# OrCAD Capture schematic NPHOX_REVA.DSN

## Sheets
1 002 Voltage Regulators: size B; title: npHOx - Voltage Regulators; rev: C; note: 100221250rA
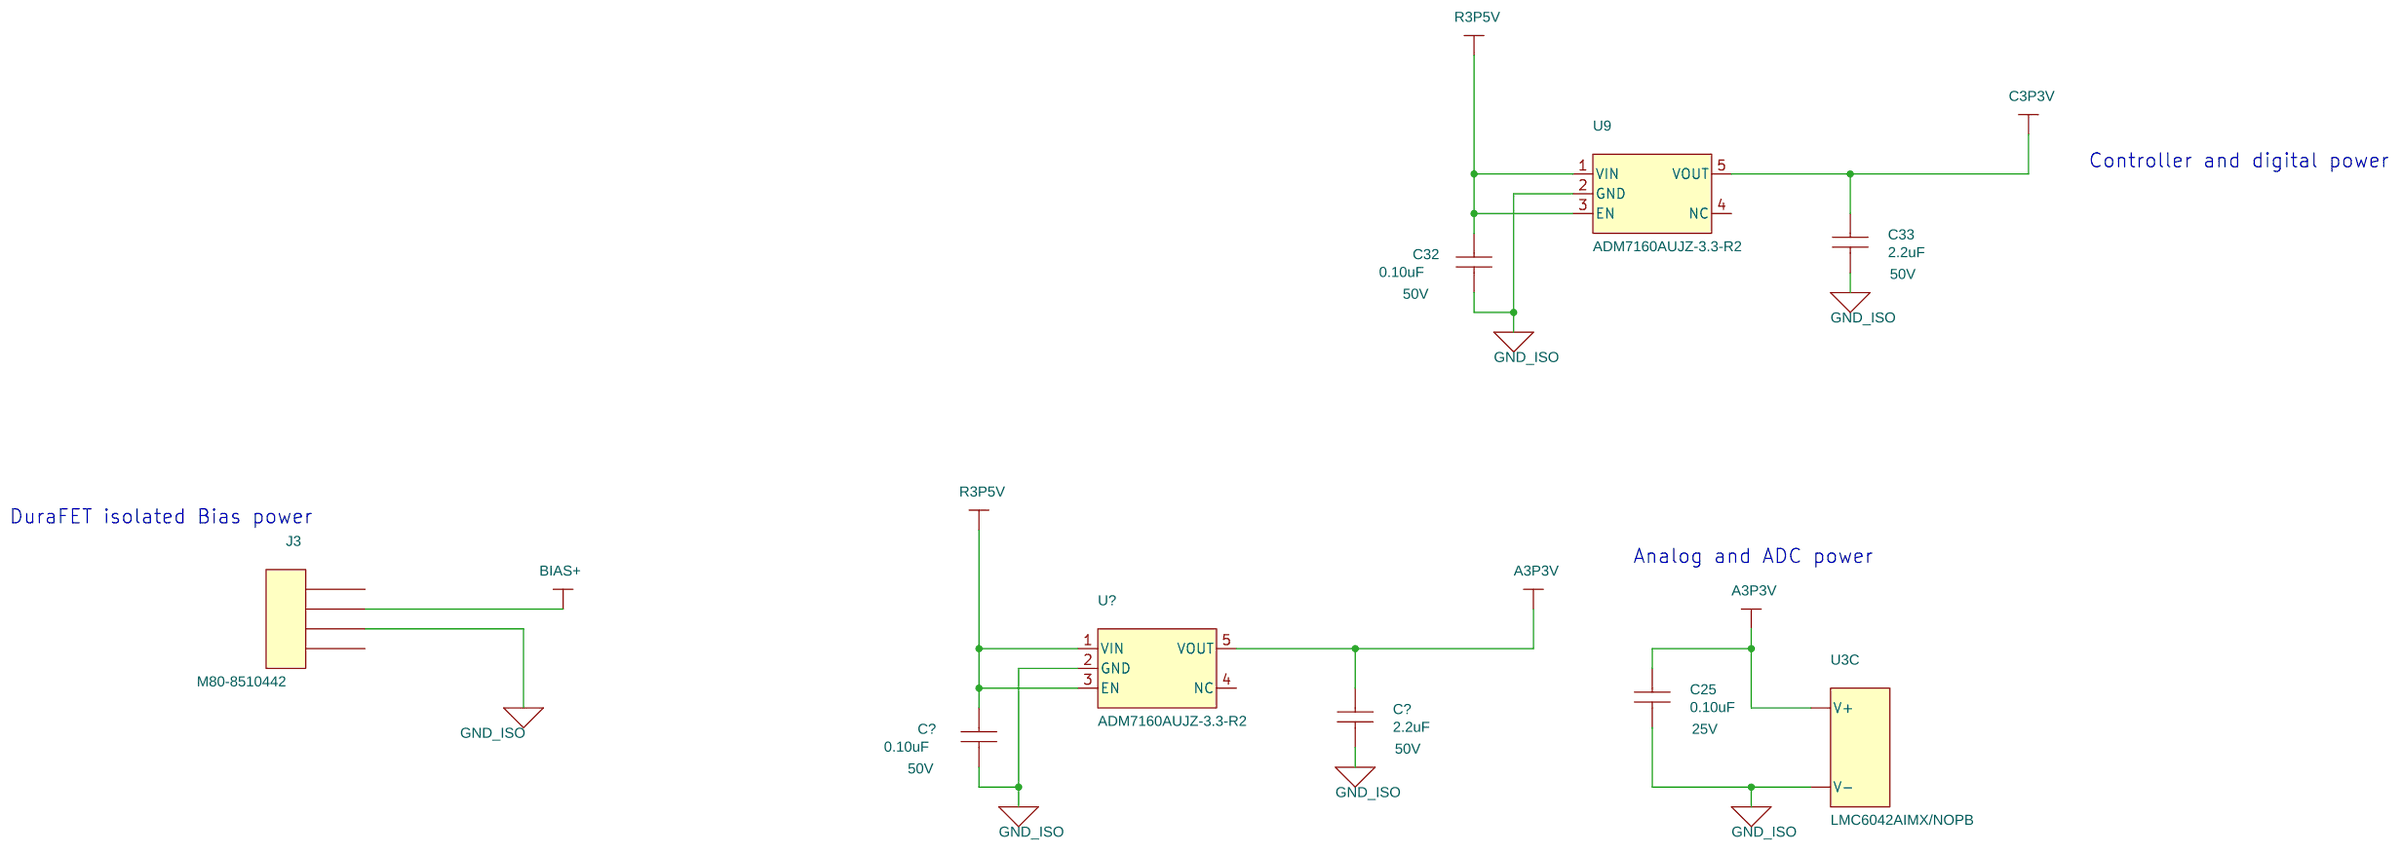
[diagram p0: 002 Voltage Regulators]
2 006 pH ADC: size B; title: npHOx - pH ADC
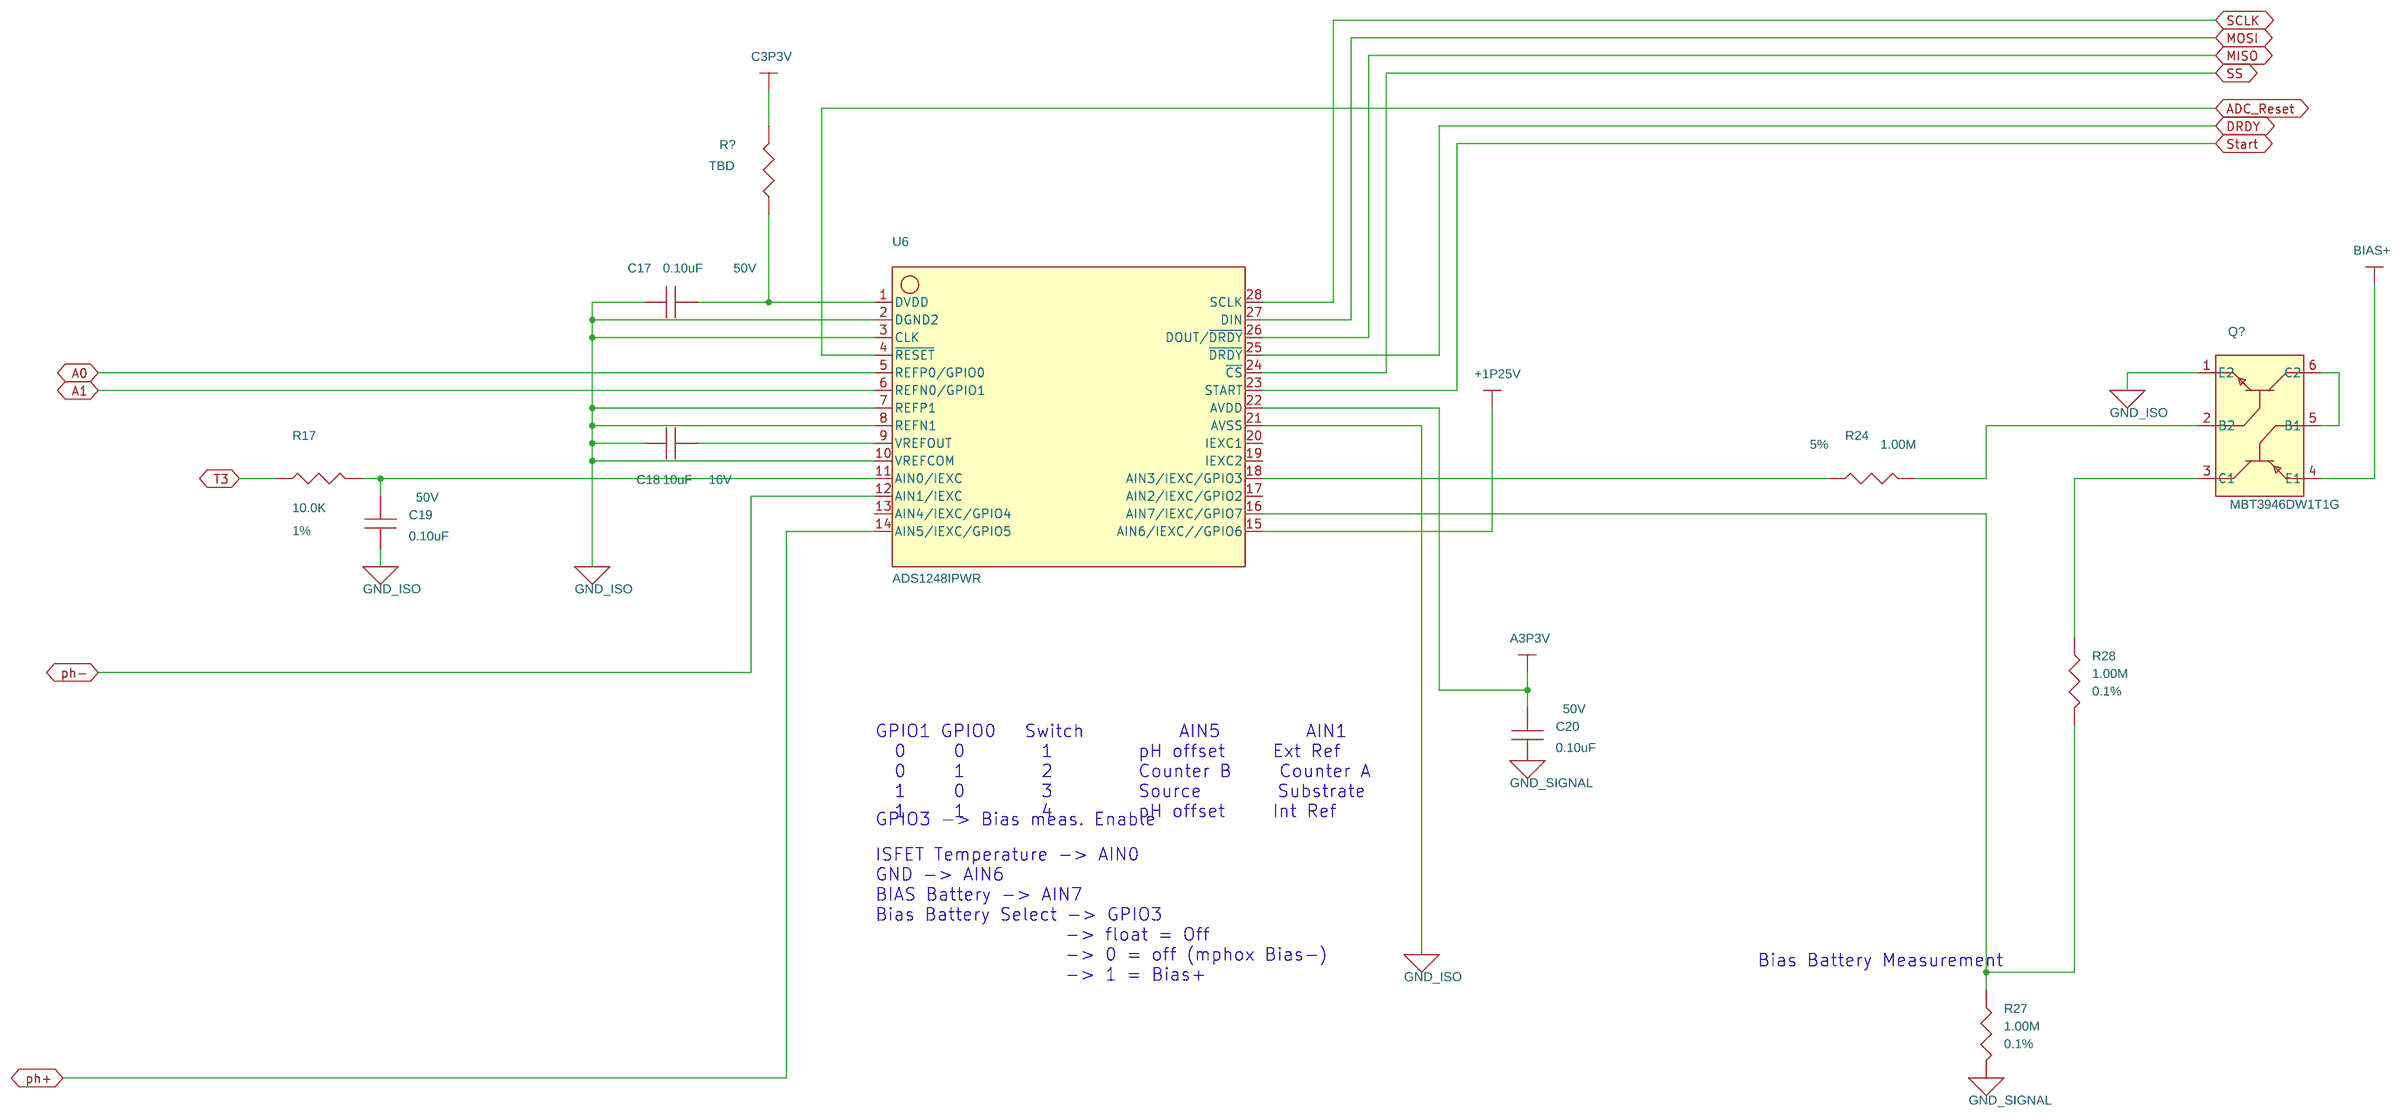
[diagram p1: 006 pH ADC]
3 007 Buffer: size B; title: npHOx - Buffer
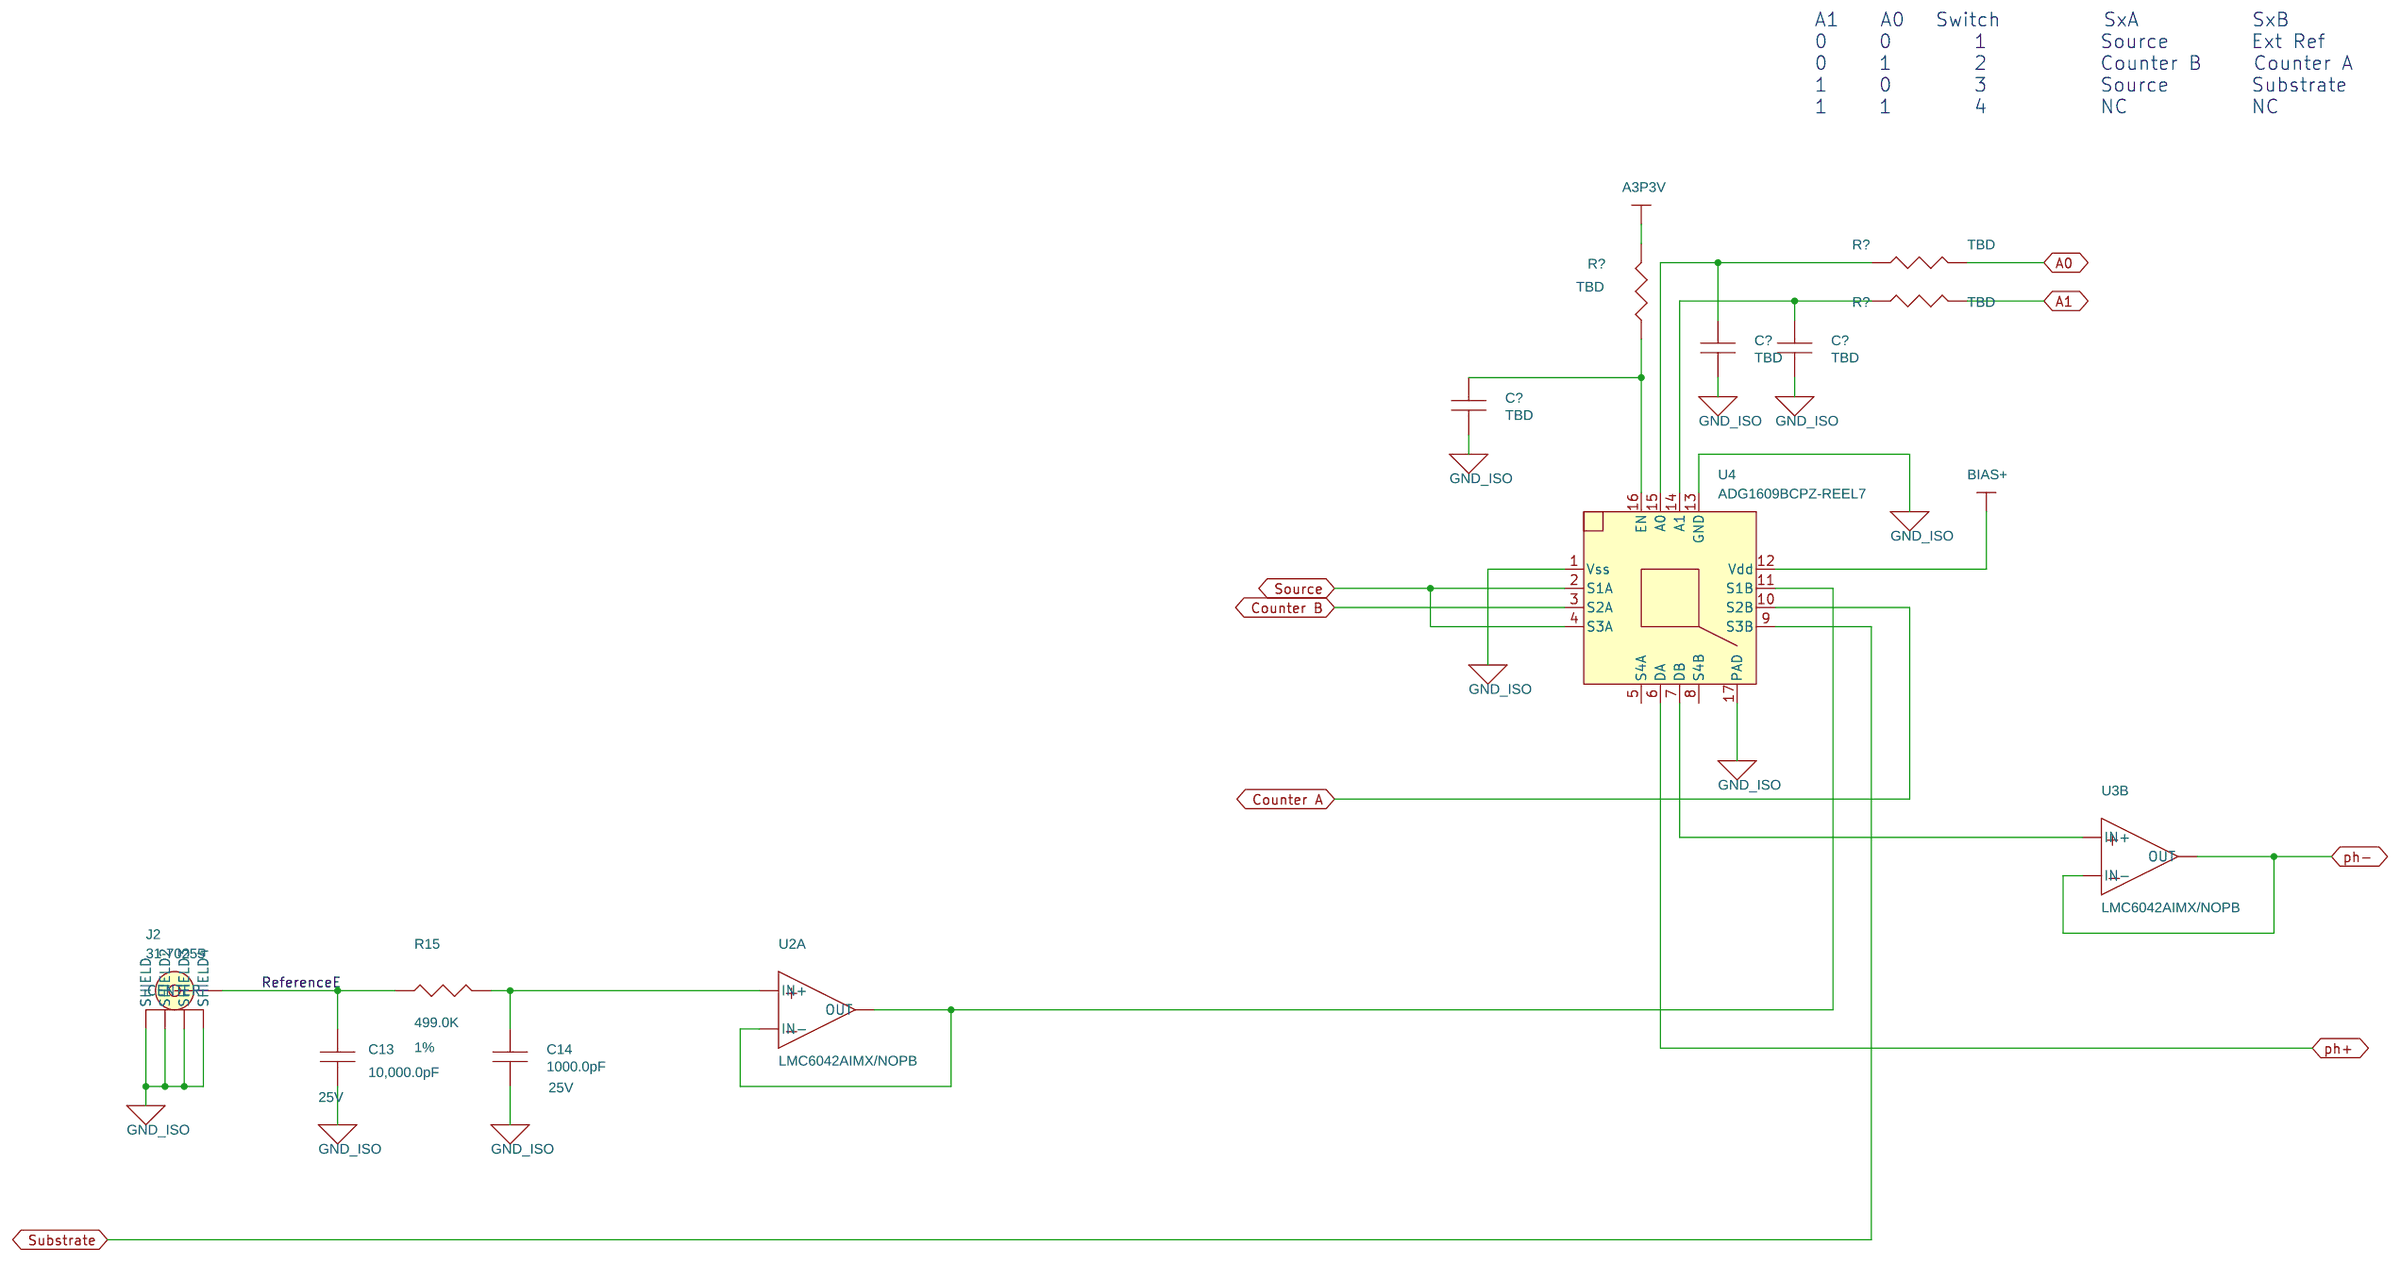
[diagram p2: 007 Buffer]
4 008 Bias: size B; title: npHOx - Bias
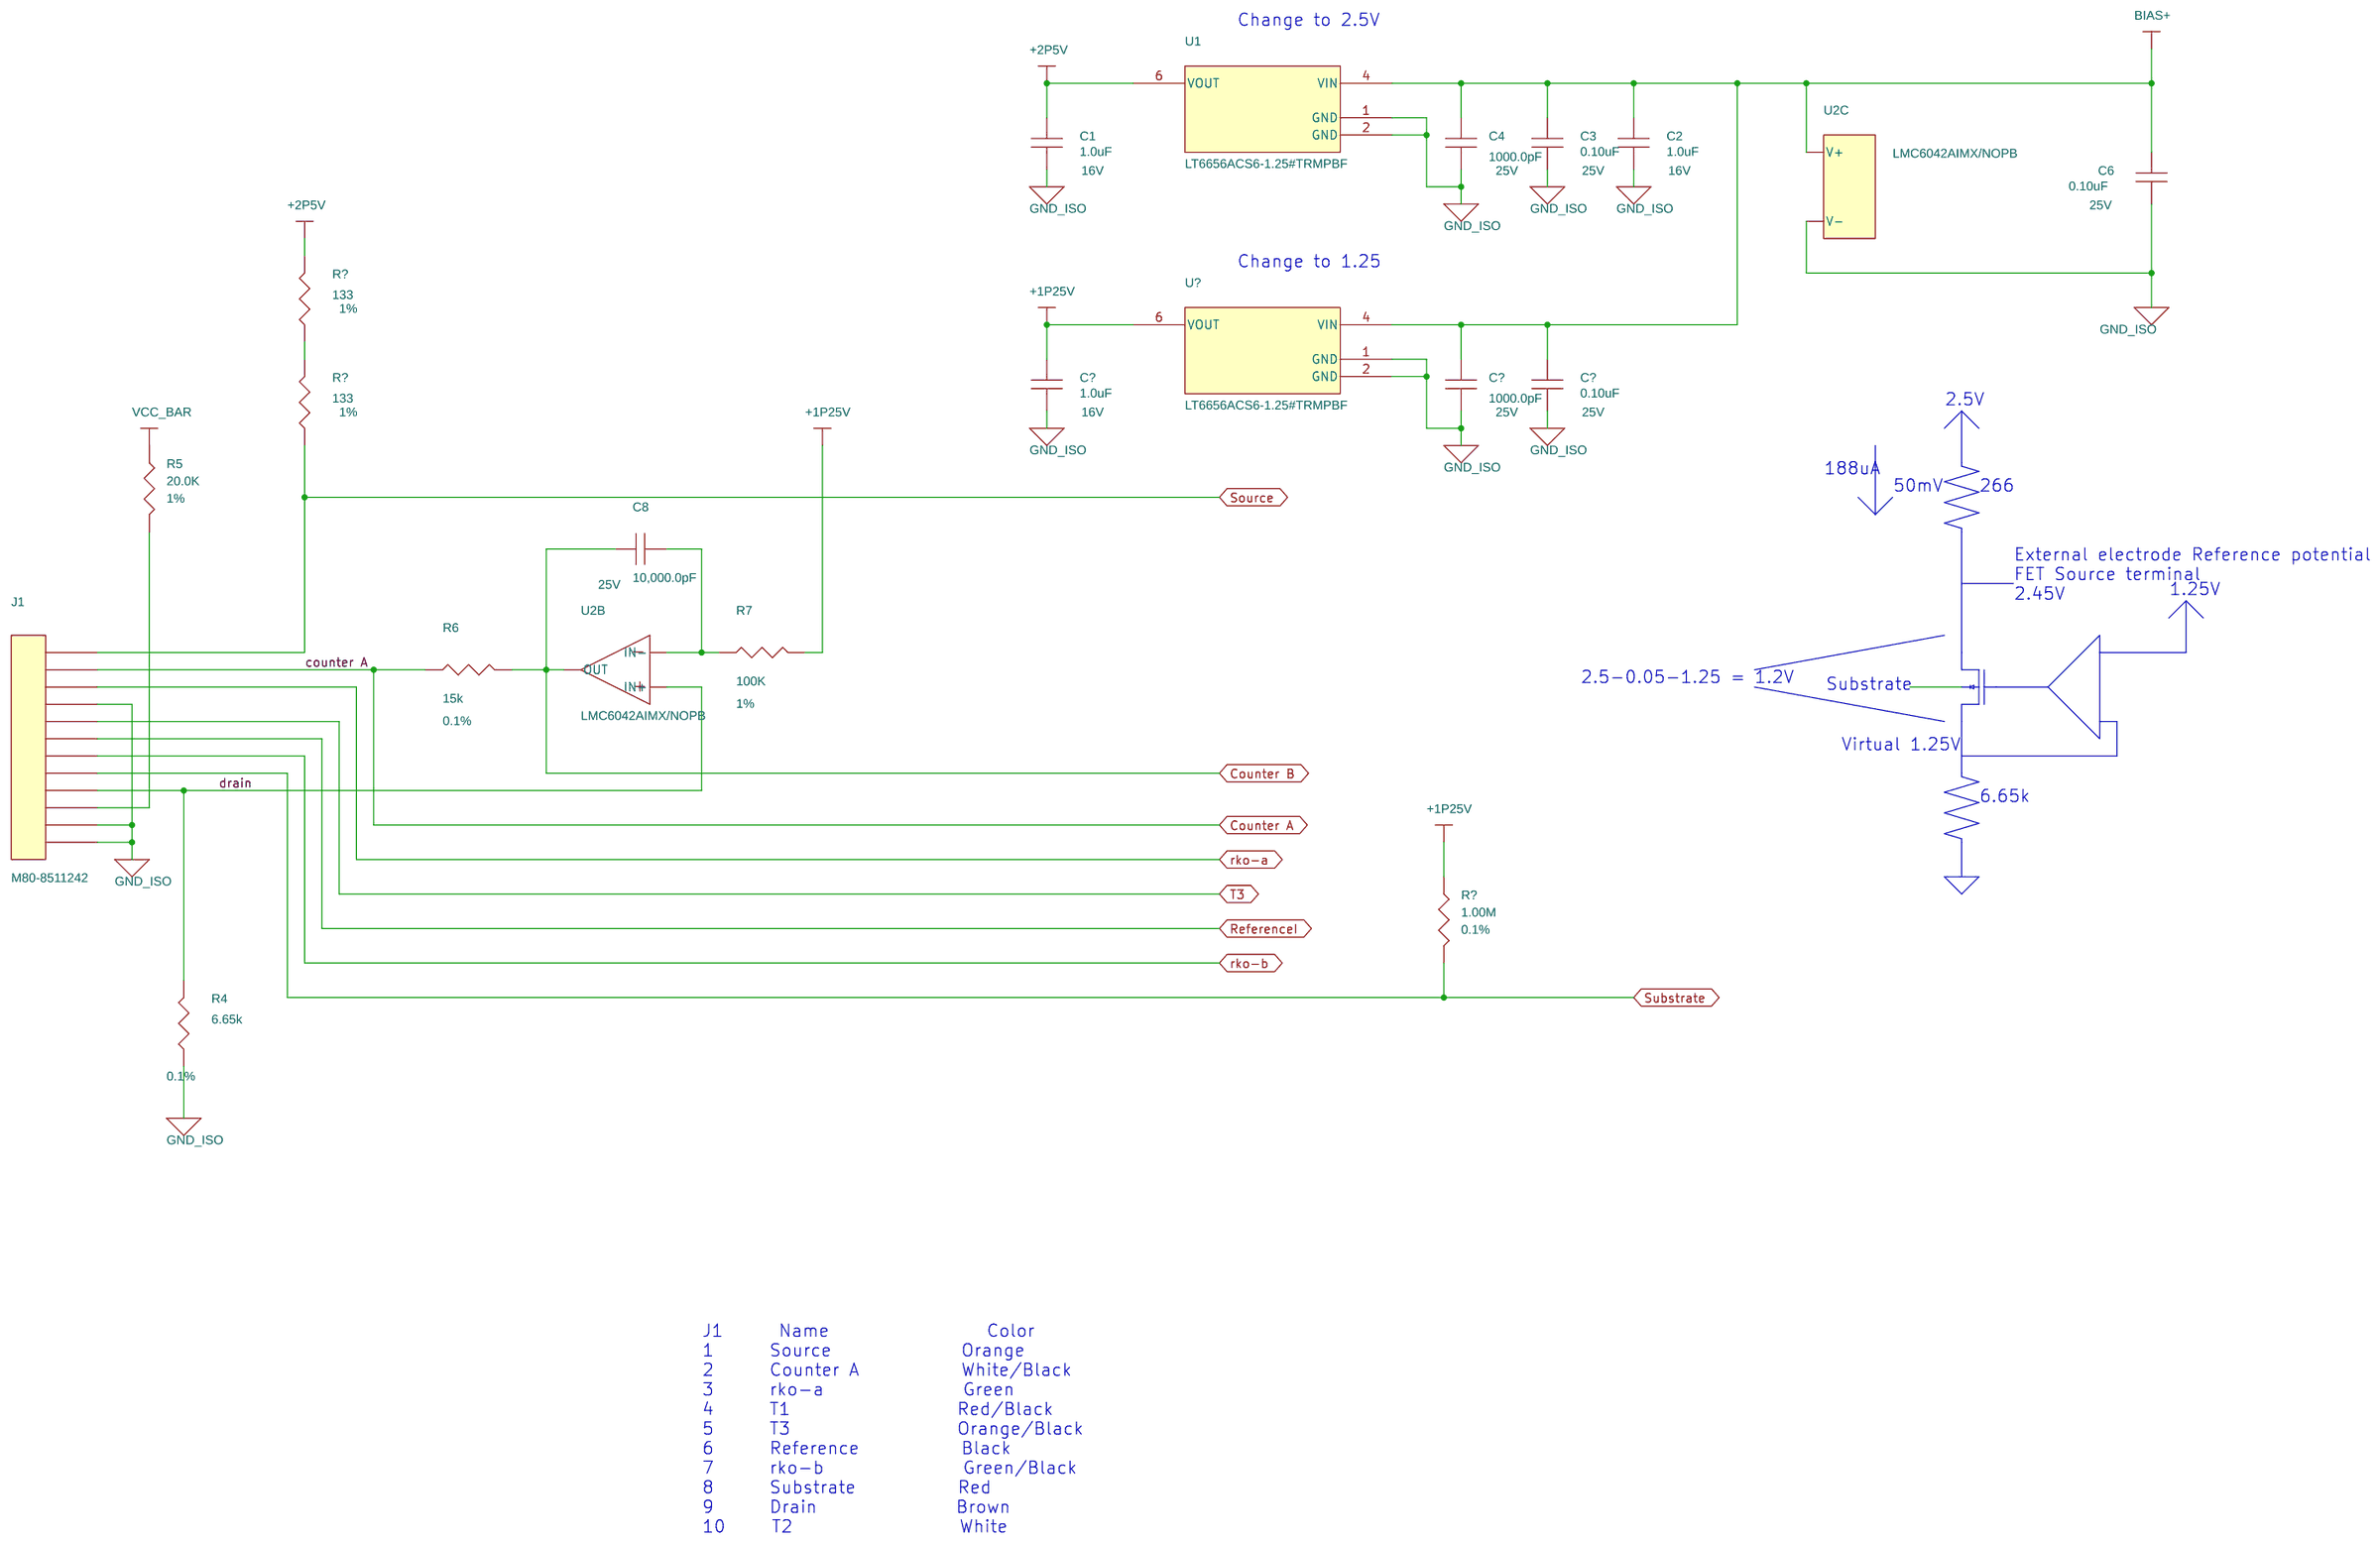
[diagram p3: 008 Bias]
5 001 Power: size B; title: npHOx - Power; rev: A
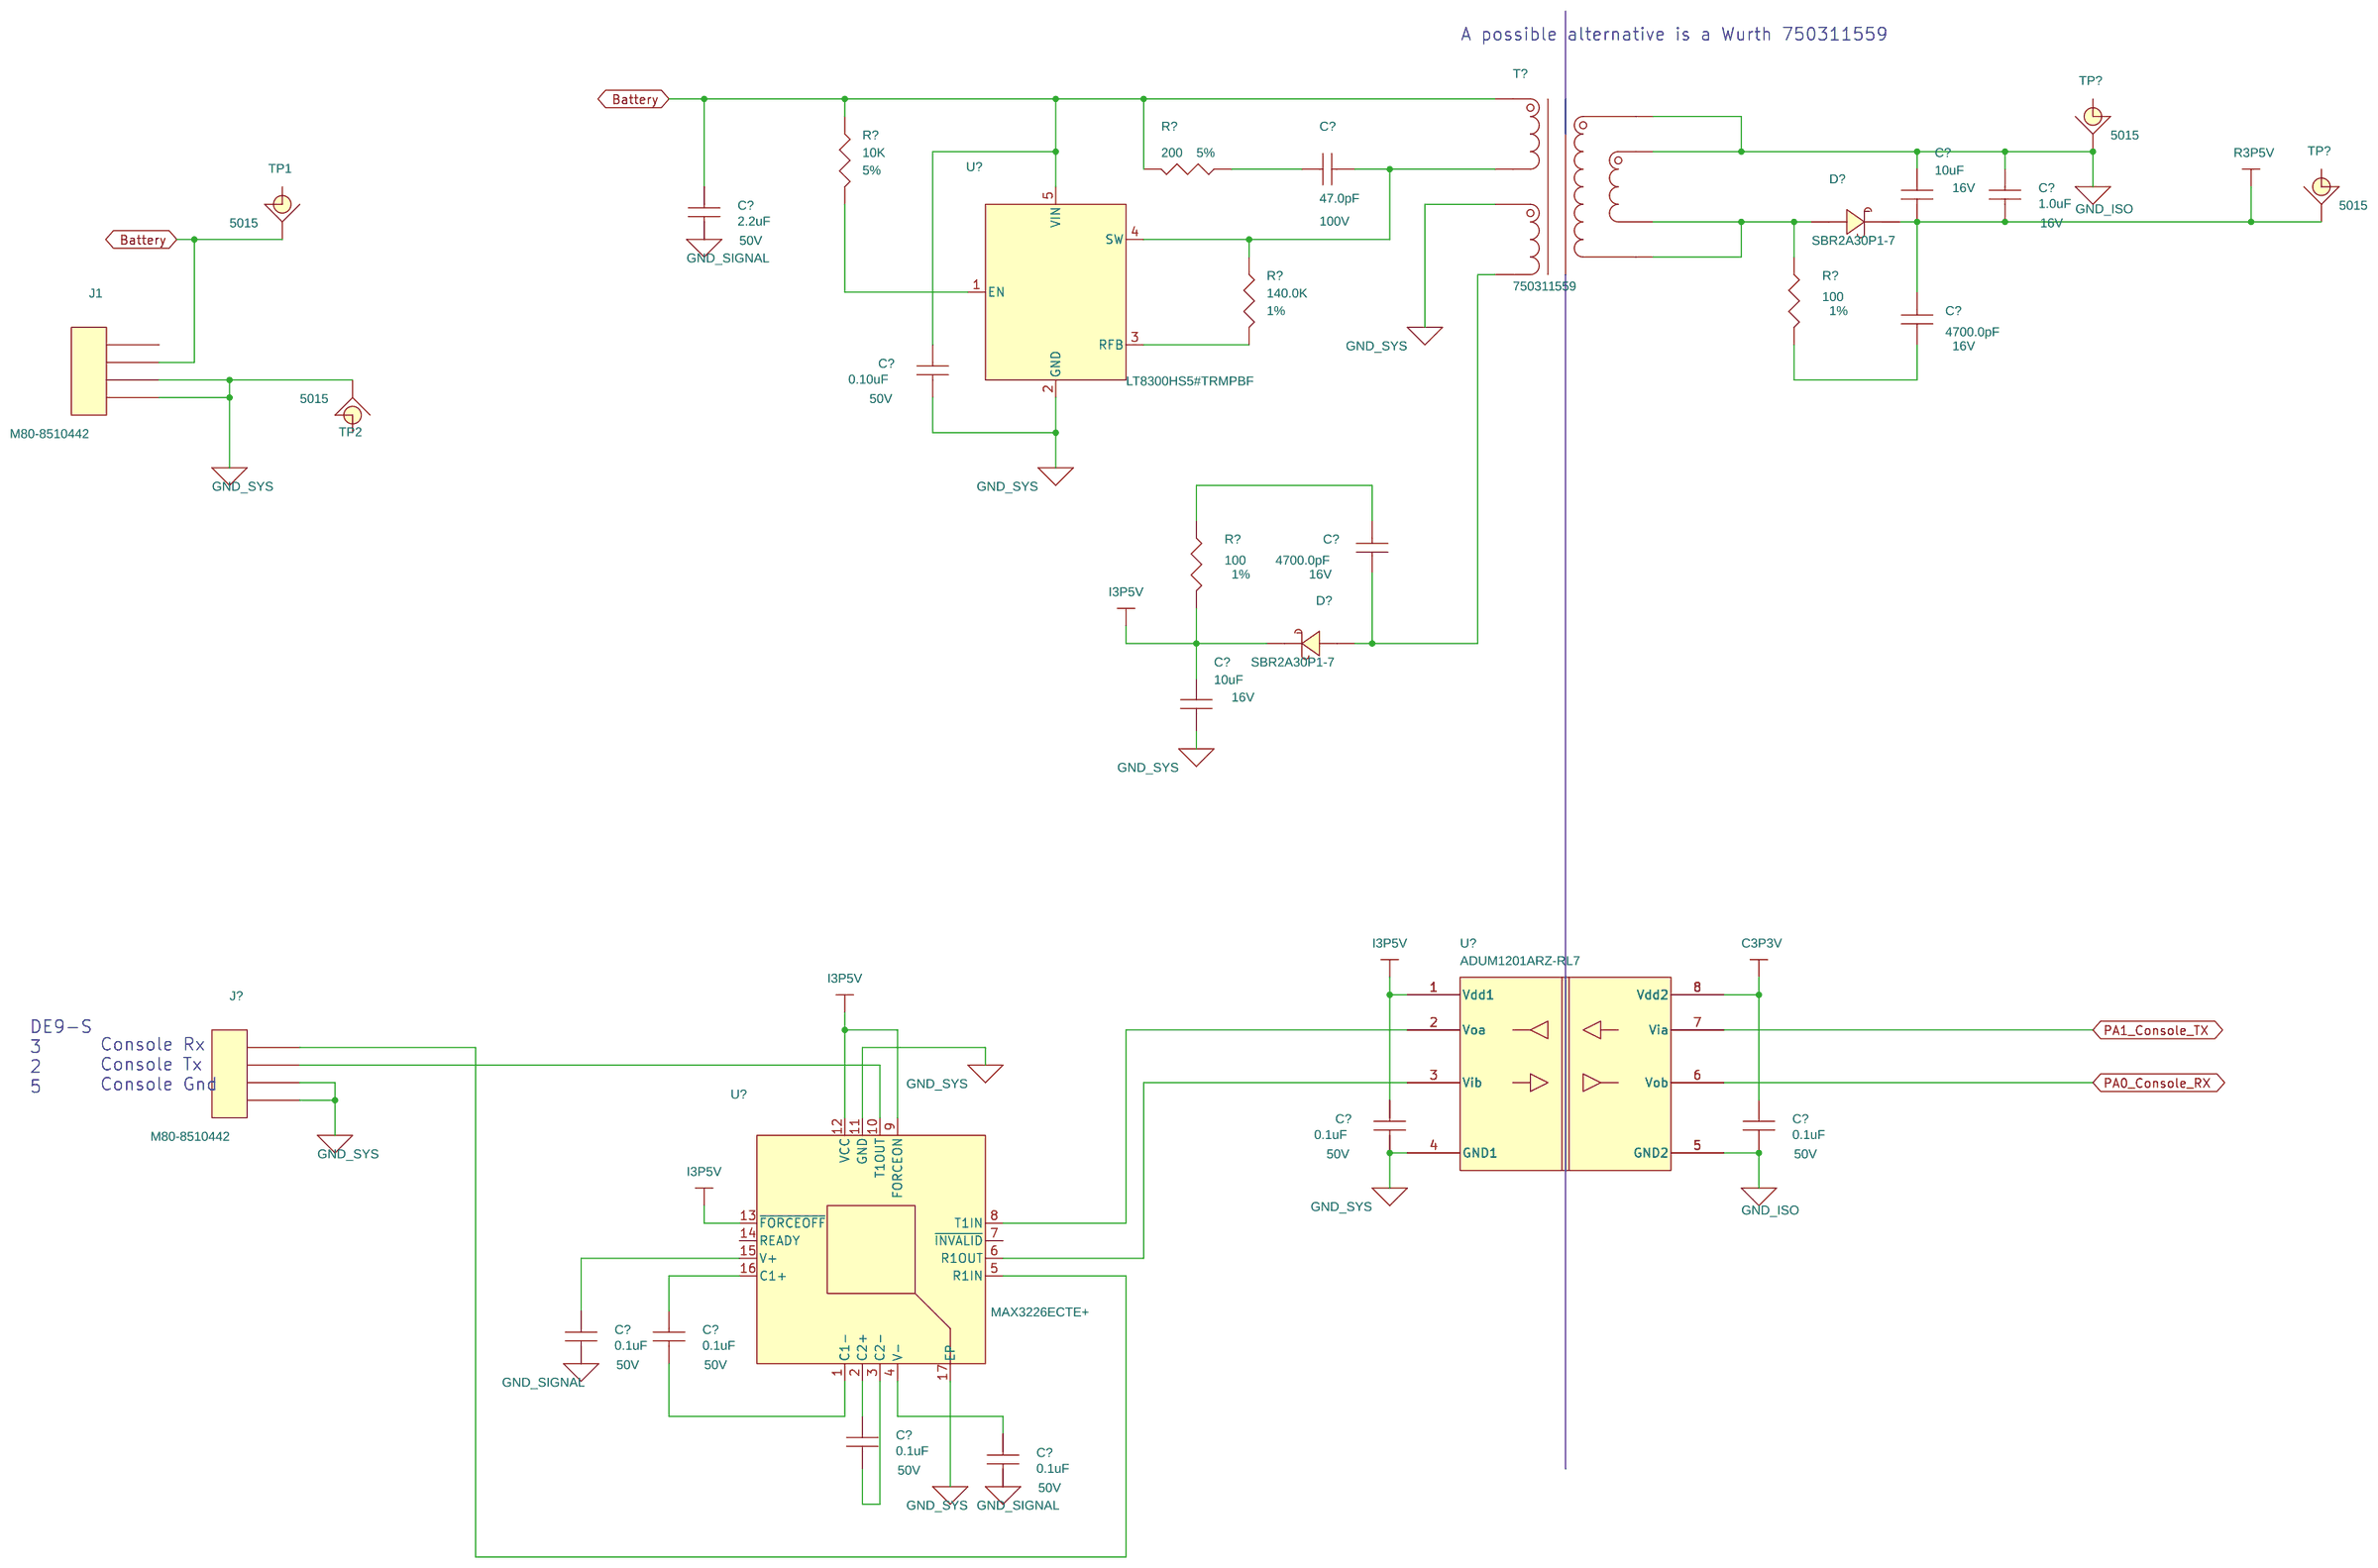
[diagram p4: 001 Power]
6 003 Processor: size B; title: npHOx - Processor; rev: A
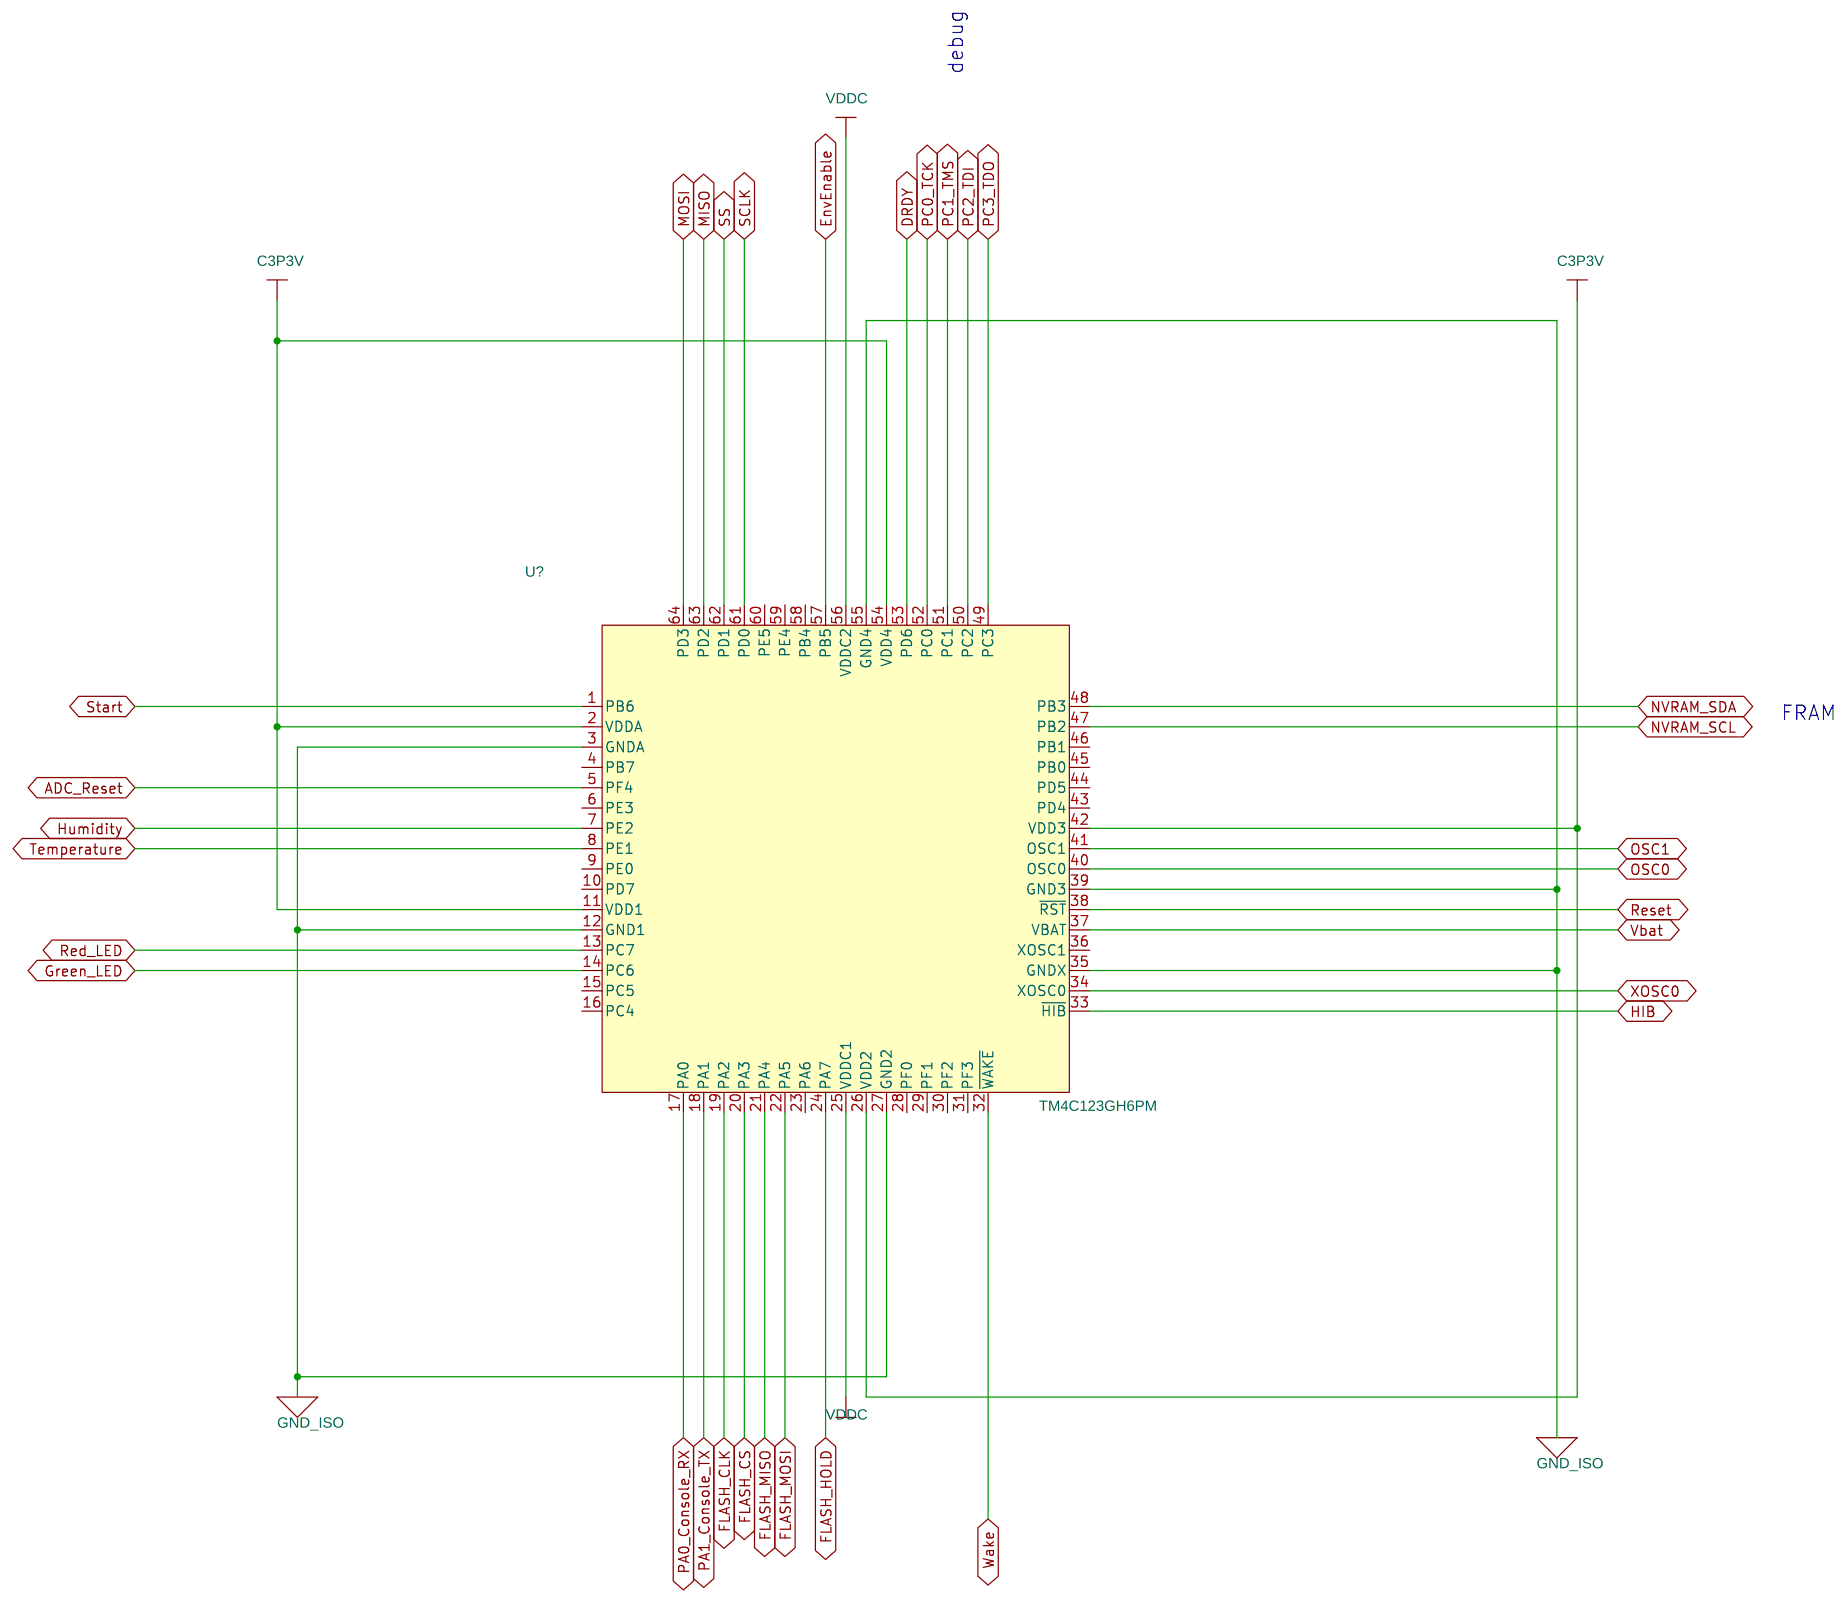
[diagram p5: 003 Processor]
7 004 Processor Bypass: size B; title: npHOx - Processor Bypass; rev: A
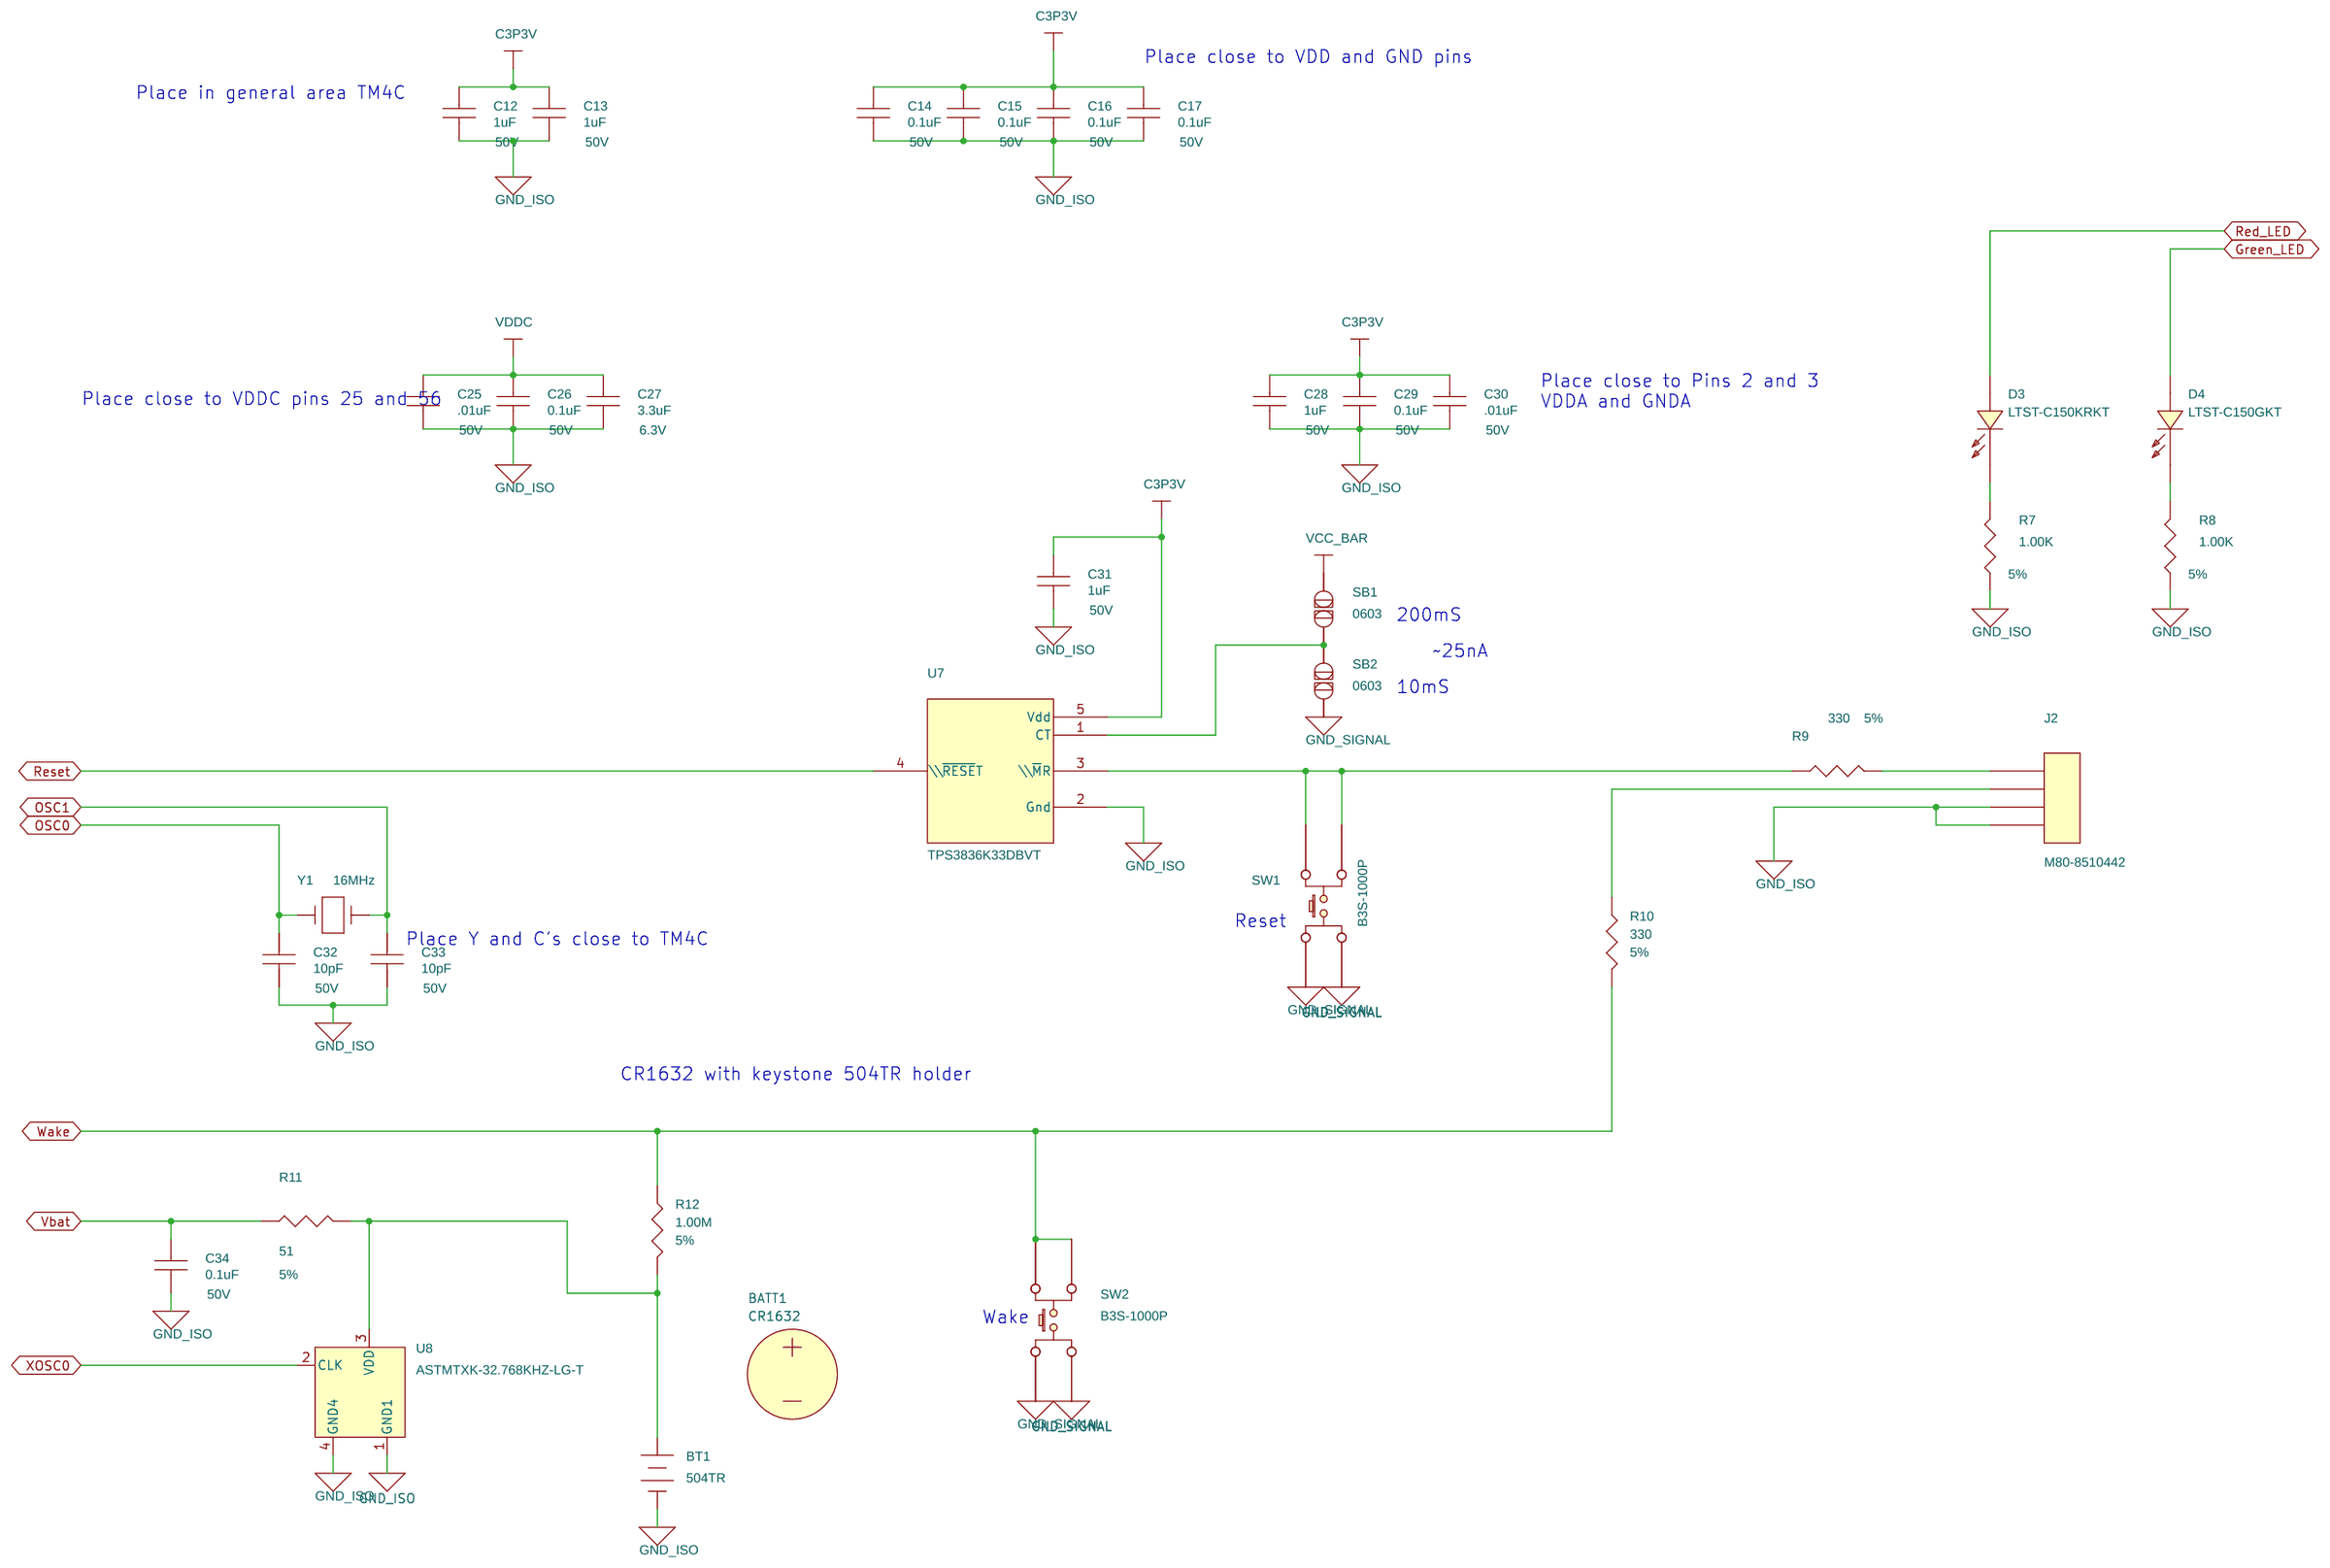
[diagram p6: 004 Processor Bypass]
8 005 Miscellaneous Interfaces: size B; title: npHOx - Miscellaneous Interfaces; rev: A
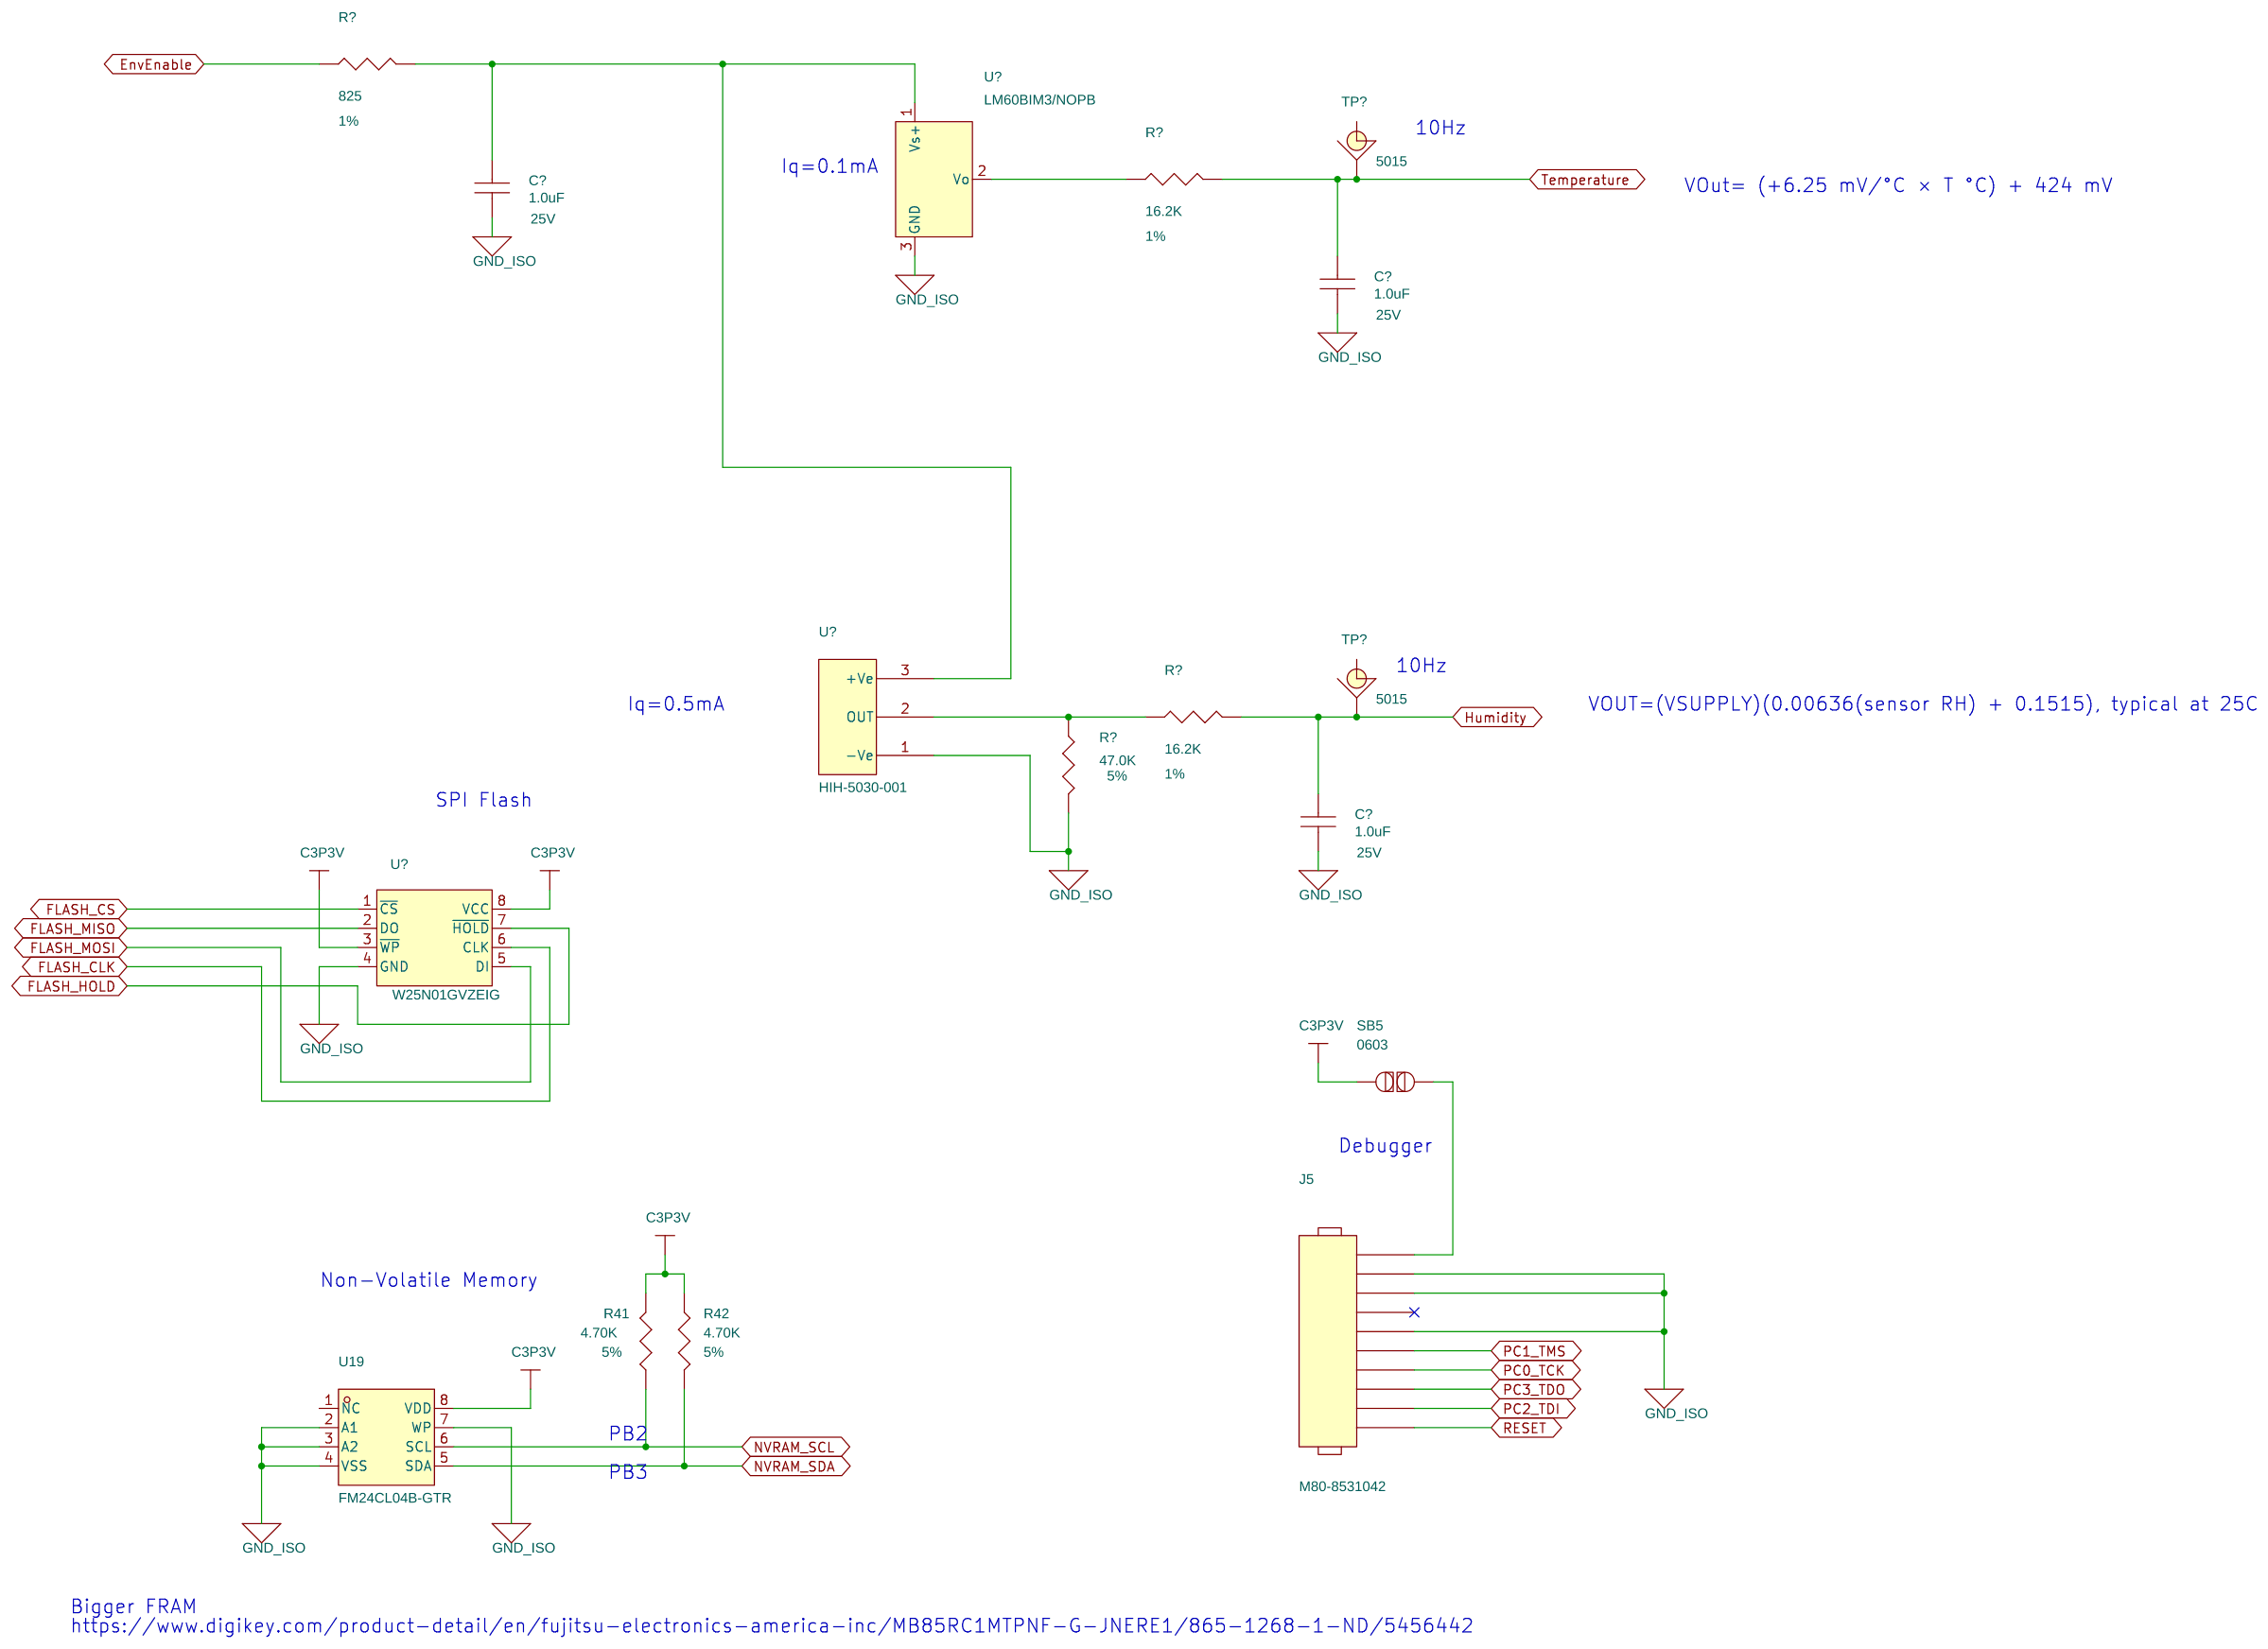
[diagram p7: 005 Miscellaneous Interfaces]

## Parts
sheet 001 Power
C?#19  1.0uF  [CAPC1608X90N]
C?#22  0.1uF  [MURATA_GCM188-0603_CAPC]
C?#23  0.10uF  [CAPC127X200X102L23N]
C?#24  0.1uF  [MURATA_GCM188-0603_CAPC]
C?#28  0.1uF  [MURATA_GCM188-0603_CAPC]
C?#30  0.1uF  [MURATA_GCM188-0603_CAPC]
C?#31  10uF  [CAPC2012X135N]
C?#33  0.1uF  [MURATA_GCM188-0603_CAPC]
C?#36  10uF  [CAPC2012X135N]
C?#38  4700.0pF  [CAPC1608X87N]
C?#39  47.0pF  [CAPC1608X87N]
C?#42  4700.0pF  [CAPC1608X87N]
C?#43  2.2uF  [CAPC2012X145N]
C?#44  0.1uF  [MURATA_GCM188-0603_CAPC]
D?#27  SBR2A30P1-7  [SODFL3717X100N]
D?#34  SBR2A30P1-7  [SODFL3717X100N]
J?#32  M80-8510442  [HARWIN_M80-851_4PIN]
R?#21  100  [RESC1608X50N]
R?#25  140.0K  [RESC1608X50N]
R?#35  200  [RESC1608X50N]
R?#40  100  [RESC1608X50N]
R?#46  10K  [RESC1608X50N]
T?#37  750311559  [WURTH_750311559]
TP1  5015  [TP_5015]
TP2  5015  [TP_5015]
TP?#26  5015  [TP_5015]
TP?#45  5015  [TP_5015]
U?#20  MAX3226ECTE+
U?#29  ADUM1201ARZ-RL7  [SOIC127P600X175-8L87N]
U?#41  LT8300HS5#TRMPBF  [SOT95P280X100-5L20N]
sheet 002 Voltage Regulators
C25  0.10uF  [CAPC1608X87N]
C32  0.10uF  [AVX_LICC-0508-A_CAPC]
C33  2.2uF  [CAPC2012X145N]
C?#2  2.2uF  [CAPC2012X145N]
C?#3  0.10uF  [AVX_LICC-0508-A_CAPC]
J3  M80-8510442  [HARWIN_M80-851_4PIN]
U3  LMC6042AIMX/NOPB  [SOIC127P600X175-8L87N]  (sections B,C)
U9  ADM7160AUJZ-3.3-R2  [SOT23-5P95_280X100L45X40N]
U?#1  ADM7160AUJZ-3.3-R2  [SOT23-5P95_280X100L45X40N]
sheet 003 Processor
U?#47  TM4C123GH6PM
sheet 004 Processor Bypass
BATT1  CR1632
BT1  504TR  [KEYSTONE_504]
C12  1uF  [CAPC160X80X90L30N]
C15  0.1uF  [MURATA_GCM188-0603_CAPC]
C16  0.1uF  [MURATA_GCM188-0603_CAPC]
C25#2  .01uF  [CAPC1608X87N]
C26  0.1uF  [MURATA_GCM188-0603_CAPC]
C27  3.3uF  [CAPC200X125X145L30N]
C28  1uF  [CAPC160X80X90L30N]
C29  0.1uF  [MURATA_GCM188-0603_CAPC]
C30  .01uF  [CAPC1608X87N]
C31  1uF  [CAPC160X80X90L30N]
C32#2  10pF  [CAPC1608X90L23N]
C33#2  10pF  [CAPC1608X90L23N]
C34  0.1uF  [MURATA_GCM188-0603_CAPC]
D3  LTST-C150KRKT  [LED_LTST-C150xxx]
D4  LTST-C150GKT  [LED_LTST-C150xxx]
R7  1.00K  [RESC1608X50N]
R8  1.00K  [RESC1608X50N]
R9  330  [RESC1608X50N]
R10  330  [RESC1608X50N]
R11  51  [RESC1608X50N]
R12  1.00M  [RESC1608X50N]
SB1  0603  [MISC_JUMPER_SM0603]
SB2  0603  [MISC_JUMPER_SM0603]
SW1  B3S-1000P  [OMRON_B3S-10xx]
SW2  B3S-1000P  [OMRON_B3S-10xx]
U7  TPS3836K33DBVT  [SOT95P280X145-5L25N]
U8  ASTMTXK-32.768KHZ-LG-T  [ABRACON_ASTMTXK]
Y1  16MHz  [XTALSC320X500X130L130N]
sheet 005 Miscellaneous Interfaces
C?#50  1.0uF  [CAPC1608X90N]
C?#52  1.0uF  [CAPC1608X90N]
C?#57  1.0uF  [CAPC1608X90N]
J5  M80-8531042  [HARWIN_M80-853_10PIN]
R41  4.70K  [RESC1608X50N]
R42  4.70K  [RESC1608X50N]
R?#49  47.0K  [RESC1608X50N]
R?#54  825  [RESC1608X50N]
R?#58  16.2K  [RESC1608X50N]
R?#59  16.2K  [RESC1608X50N]
SB5  0603  [MISC_JUMPER_SM0603]
TP?#51  5015  [TP_5015]
TP?#56  5015  [TP_5015]
U19  FM24CL04B-GTR  [CYPRESS_SOIC_8PIN]
U?#48  LM60BIM3/NOPB  [SOT95P237X112-3L40N_132]
U?#53  HIH-5030-001  [HONEYWELL_HIH-5030]
U?#55  W25N01GVZEIG
sheet 006 pH ADC
C17  0.10uF  [CAPC1608X87N]
C17#2  0.10uF  [CAPC1608X87N]
C18  10uF  [CAPC3216X180N]
C19  0.10uF  [CAPC1608X87N]
C20  0.10uF  [CAPC1608X87N]
Q?#5  MBT3946DW1T1G  [ONSEMI_SC-88_6PIN]
R17  10.0K  [RESC1608X50N]
R24  1.00M  [RESC1608X50N]
R27  1.00M  [RESC200X125X55L40N]
R28  1.00M  [RESC200X125X55L40N]
R?#4  TBD  [MBARI_TBD0603_RESC]
U6  ADS1248IPWR  [SOP28P65_970X640X120L62X24N]
sheet 007 Buffer
C13  10,000.0pF  [CAPC1608X87N]
C13#2  10,000.0pF  [CAPC1608X87N]
C14  1000.0pF  [CAPC1608X87N]
C14#2  1000.0pF  [CAPC1608X87N]
C?#6  TBD  [MBARI_TBD0603_CAPC]
C?#8  TBD  [MBARI_TBD0603_CAPC]
C?#9  TBD  [MBARI_TBD0603_CAPC]
J2  31-70255  [AMP_31-70255]
R15  499.0K  [RESC1608X50N]
R?#7  TBD  [MBARI_TBD0603_RESC]
R?#10  TBD  [MBARI_TBD0603_RESC]
R?#11  TBD  [MBARI_TBD0603_RESC]
U4  ADG1609BCPZ-REEL7  [QFN17P50_300X300X80L40X24T160N]
sheet 008 Bias
C1  1.0uF  [CAPC1608X90N]
C2  1.0uF  [CAPC1608X90N]
C3  0.10uF  [CAPC1608X87N]
C4  1000.0pF  [CAPC1608X87N]
C6  0.10uF  [CAPC1608X87N]
C8  10,000.0pF  [CAPC1608X87N]
C?#14  1000.0pF  [CAPC1608X87N]
C?#16  0.10uF  [CAPC1608X87N]
C?#17  1.0uF  [CAPC1608X90N]
J1  M80-8511242  [HARWIN_M80-8511242]
R4  6.65k  [RESC160X80X55L30N]
R5  20.0K  [RESC1608X50N]
R6  15k  [RESC160X80X55L30N]
R7#2  100K  [VISHAY_CRCW-0603_RESC]
R?#12  1.00M  [RESC200X125X55L40N]
R?#15  133  [RESC1608X50N]
R?#18  133  [RESC1608X50N]
U1  LT6656ACS6-1.25#TRMPBF  [SOT95P280X100-6L20N]
U2  LMC6042AIMX/NOPB  [SOIC127P600X175-8L87N]  (sections A,B,C)
U?#13  LT6656ACS6-1.25#TRMPBF  [SOT95P280X100-6L20N]

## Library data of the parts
C1 C2 C?#17 C?#19 = CAP: CLASS: DISCRETE; Dielectric Type: Ceramic; Manufacturer: Kemet; Manufacturer PN: C0603C105K4RAC; PART_NUMBER: C0603C105K4RAC; Package Size: 0603; Rated Voltage: 16V; Temperature Coefficient: X7R; Tolerance: 10%
C15 C16 C26 C29 C34 C?#22 C?#24 C?#28 C?#30 C?#33 C?#44 = CAP: CAP CER 0.1UF 50V X7R 0603; CLASS: DISCRETE; Manufacturer: Murata Electronics North America; Manufacturer PN: GCM188R71H104KA57J; PART_NUMBER: GCM188R71H104KA57J; Package Size: 0603 (1608 Metric); Rated Voltage: 50V; Temperature Coefficient: X7R; Tolerance: 10%
C32 C?#3 C?#23 = CAP: CAP CER 0.1UF 50V X7R 0508; CLASS: DISCRETE; Dielectric Type: Capacitors; Manufacturer: AVX Corporation; Manufacturer PN: 05085C104KAJ2A; PART_NUMBER: 05085C104KAJ2A; Package Size: 0508 (1220 Metric); Rated Voltage: 50V; Temperature Coefficient: X7R; Tolerance: 10%
C?#31 C?#36 = CAP: CAP CER 10UF 16V 20% X7R 0805; CLASS: DISCRETE; Dielectric Type: Capacitors; Manufacturer: Taiyo Yuden; Manufacturer PN: EMK212BB7106MG-T; PART_NUMBER: EMK212BB7106MG-T; Package Size: 0805 (2012 Metric); Rated Voltage: 16V; TMP Manufacturer: Kemet; TMP Manufacturer PN: C1206C475K4RAC; Temperature Coefficient: X7R; Tolerance: ±20%
C?#38 C?#42 = CAP: CLASS: DISCRETE; Dielectric Type: Ceramic; Manufacturer: Kemet; Manufacturer PN: C0603C472K4RAC; PART_NUMBER: C0603C472K4RAC; Package Size: 0603; Rated Voltage: 16V; Temperature Coefficient: X7R; Tolerance: 10%
C?#39 = CAP: CLASS: DISCRETE; Dielectric Type: Ceramic; Manufacturer: Kemet; Manufacturer PN: C0603C470J1GAC; PART_NUMBER: C0603C470J1GAC; Package Size: 0603; Rated Voltage: 100V; TMP Manufacturer: Kemet; TMP Manufacturer PN: C0603C470J1GAC; Temperature Coefficient: C0G(NP0); Tolerance: 5%
C?#43 = CAP: CAP CER 2.2UF 50V 10% X7R 0805; CLASS: DISCRETE; Dielectric Type: Capacitors; Manufacturer: Taiyo Yuden; Manufacturer PN: UMK212BB7225KG-T; PART_NUMBER: UMK212BB7225KG-T; Package Size: 0805 (2012 Metric); Rated Voltage: 50V; TMP Manufacturer: Kemet; TMP Manufacturer PN: C1206C225K4RACTU; Temperature Coefficient: X7R; Tolerance: ±10%
D?#27 D?#34 = DIODE_SBR: DIODE SBR 30V 2A POWERDI123; CLASS: DISCRETE; Manufacturer: Diodes Incorporated; Package Size: 2-SMD, Flat Lead; Rated Voltage: 450mV @ 2A; TMP Manufacturer: Diodes Incorporated
J3 J?#32 = CON4: CONN HDR 2MM R/A W/LATCH 4POS; CLASS: IO; Manufacturer: Harwin Inc
R?#21 R?#40 = RES: RES SMD 100 OHM 1% 1/10W 0603; CLASS: DISCRETE; Manufacturer: Vishay; Manufacturer PN: CRCW0603100RFKEA; PART_NUMBER: CRCW0603100RFKEA; Package Size: 0603; Rated Power: 0.1W; Temperature Coefficient: 100ppm/K; Tolerance: 1%
R?#25 = RES: CLASS: DISCRETE; Manufacturer: Vishay; Manufacturer PN: CRCW0603140KFKEA; PART_NUMBER: CRCW0603140KFKEA; Package Size: 0603; Rated Power: 0.1W; TMP Manufacturer: Vishay; TMP Manufacturer PN: CRCW0603140KFKEA; Temperature Coefficient: 100ppm/K; Tolerance: 1%
R?#35 = RES: CLASS: DISCRETE; Manufacturer: Vishay; Manufacturer PN: CRCW0603200RJNEA; PART_NUMBER: CRCW0603200RJNEA; Package Size: 0603; Rated Power: 0.1W; TMP Manufacturer: Vishay; TMP Manufacturer PN: CRCW0603200RJNEA; Temperature Coefficient: 200ppm/K; Tolerance: 5%
R?#46 = RES: RES 10K OHM 1/10W 5% 0603 SMD; CLASS: DISCRETE; Manufacturer: Vishay/Dale; Manufacturer PN: CRCW060310K0JNEA; PART_NUMBER: CRCW060310K0JNEA; Package Size: 0603; Rated Power: 0.1W; TMP Manufacturer: Vishay; TMP Manufacturer PN: CRCW060310K0JNEA; Temperature Coefficient: 200ppm/K; Tolerance: 5%
T?#37 = WURTH_750311559: FLYBACK TRANSFORMER WE-FB LT8300; CLASS: DISCRETE; Manufacturer: Wurth Electronics Midcom; Package Size: 9.77mm L x 9.14mm W
TP1 TP2 = TESTPOINT: PC TEST POINT MINIATURE SMT; CLASS: DISCRETE; Manufacturer: Keystone Electronics; Package Size: 2.67 x 1.02 mm
TP?#26 TP?#45 TP?#51 TP?#56 = TESTPOINT: PC TEST POINT MINIATURE SMT; CLASS: DISCRETE; Manufacturer: Keystone Electronics; Package Size: 2.67 x 1.02 mm; TMP Manufacturer: Keystone Electronics
U?#20 = MAX3226ECTE+
U?#29 = ADuM1201: IC DGTL ISO 2CH LOGIC 8SOIC; CLASS: IC; Manufacturer: Analog Devices Inc; Package Size: 8-SOIC (0.154", 3.90mm Width); Supply Voltage: 2.7 V ~ 5.5 V
U?#41 = LT8300: IC REG FLYBACK ISO ADJ TSOT23-5; CLASS: IC; Manufacturer: Linear Technology; Package Size: SOT-23-5 Thin, TSOT-23-5; TMP Manufacturer: Linear Technology
C3 C6 C25 C?#16 = CAP: CAP CER 0.1UF 25V 10% X7R 0603; CLASS: DISCRETE; Dielectric Type: Ceramic; Manufacturer: Kemet; Manufacturer PN: C0603C104K3RACTU; PART_NUMBER: C0603C104K3RAC; Package Size: 0603; Rated Voltage: 25V; Temperature Coefficient: X7R; Tolerance: 10%
C33 C?#2 = CAP: CAP CER 2.2UF 50V 10% X7R 0805; CLASS: DISCRETE; Dielectric Type: Capacitors; Manufacturer: Taiyo Yuden; Manufacturer PN: UMK212BB7225KG-T; PART_NUMBER: UMK212BB7225KG-T; Package Size: 0805 (2012 Metric); Rated Voltage: 50V; Temperature Coefficient: X7R; Tolerance: ±10%
U2 U3 = LMC6042: IC OPAMP GP 100KHZ RRO 8SOIC; CLASS: IC; Manufacturer: Texas Instruments; Package Size: 8-SOIC (0.154", 3.90mm Width); Supply Voltage: 4.5 V - 15.5 V, 2.25 V - 7.75 V
U9 U?#1 = ADM7160_UJ-5: IC REG LINEAR 3.3V 200MA TSOT5; CLASS: IC; Manufacturer: Analog Devices Inc.; Package Size: SOT-23-5 Thin, TSOT-23-5
U?#47 = TM4C123GH6PM
BATT1 = BATT_COIN: BATTERY LITHIUM COIN 3V 16MM; CLASS: DISCRETE; Manufacturer: Panasonic - BSG; Package Size: 0.63" Dia x 0.13" H (16.0mm x 3.2mm)
BT1 = BATTERY: SMT HOLDER 16MM CELL; CLASS: DISCRETE; Manufacturer: Keystone Electronics
C12 C28 C31 = CAP: CAP CER 1UF 50V X5R 0603; CLASS: DISCRETE; Dielectric Type: Capacitors; Manufacturer: TDK Corporation; Manufacturer PN: C1608X5R1H105K080AB; PART_NUMBER: C1608X5R1H105K080AB; Package Size: 0603 (1608 Metric); Rated Voltage: 50V; Temperature Coefficient: X5R; Tolerance: 10%
C25#2 C30 = CAP: CLASS: DISCRETE; Dielectric Type: Ceramic; Manufacturer: Kemet; Manufacturer PN: C0603C103K5RAC; PART_NUMBER: C0603C103K5RAC; Package Size: 0603; Rated Voltage: 50V; Temperature Coefficient: X7R; Tolerance: 10%
C27 = CAP: CAP CER 3.3UF 6.3V X7R 0805; CLASS: DISCRETE; Dielectric Type: Capacitors; Manufacturer: TDK Corporation; Manufacturer PN: CGJ4J2X7R0J335K125AA; PART_NUMBER: CGJ4J2X7R0J335K125AA; Package Size: 0805 (2012 Metric); Rated Voltage: 6.3V; Temperature Coefficient: X7R; Tolerance: 10%
C32#2 C33#2 = CAP: CAP CER 10PF 50V C0G 0603; CLASS: DISCRETE; Dielectric Type: Capacitors; Manufacturer: TDK Corporation; Manufacturer PN: C1608C0G1H100D080AA; PART_NUMBER: C1608C0G1H100D080AA; Package Size: 0603 (1608 Metric); Rated Voltage: 50V; Temperature Coefficient: C0G, NP0; Tolerance: 0.5pF
D3 = LED: LED SUPER RED CLEAR 1206 SMD; CLASS: DISCRETE; LED Color: Red; Manufacturer: Lite-On Inc; Package Size: 1206 (3216 Metric); Rated Voltage: 2V
D4 = LED: LED GREEN CLEAR 1206 SMD; CLASS: DISCRETE; LED Color: Green; Manufacturer: Lite-On Inc; Package Size: 1206 (3216 Metric); Rated Voltage: 2.1V
R7 R8 = RES: RES 1.0K OHM 1/10W 5% 0603 SMD; CLASS: DISCRETE; Manufacturer: Vishay/Dale; Manufacturer PN: CRCW06031K00JNEA; PART_NUMBER: CRCW06031K00JNEA; Package Size: 0603; Rated Power: 0.1W; TMP Manufacturer: Vishay; TMP Manufacturer PN: CRCW0603270RJNEA; Temperature Coefficient: 200ppm/K; Tolerance: 5%
R9 R10 = RES: RES SMD 330 OHM 5% 1/10W 0603; CLASS: DISCRETE; Manufacturer: Vishay; Manufacturer PN: CRCW0603330RJNEA; PART_NUMBER: CRCW0603330RJNEA; Package Size: 0603; Rated Power: 0.1W; Temperature Coefficient: 200ppm/K; Tolerance: 5%
R11 = RES: CLASS: DISCRETE; Manufacturer: Vishay; Manufacturer PN: CRCW060351R0JNEA; PART_NUMBER: CRCW060351R0JNEA; Package Size: 0603; Rated Power: 0.1W; Temperature Coefficient: 200ppm/K; Tolerance: 5%
R12 R24 = RES: RES SMD 1M OHM 5% 1/10W 0603; CLASS: DISCRETE; Manufacturer: Vishay; Manufacturer PN: CRCW06031M00JNEA; PART_NUMBER: CRCW06031M00JNEA; Package Size: 0603; Rated Power: 0.1W; Temperature Coefficient: 200ppm/K; Tolerance: 5%
SB1 SB2 SB5 = SB_JUMPER: MISC 2 PIN JUMPER SOLDER BRIDGE 0603; CLASS: IO; PART_NUMBER: MISC_SOLDERBRIDGE_SM0603
SW1 SW2 = SW_SPST_12_34: SWITCH TACTILE SPST-NO 0.05A 24V; CLASS: DISCRETE; Manufacturer: Omron Electronics Inc-EMC Div; Package Size: 6.60mm x 6.00mm
U7 = TPS3836: IC 2.93V LOW CURRENT MONSOT-23-5; CLASS: IC; Manufacturer: Texas Instruments; Package Size: SC-74A, SOT-753
U8 = ABRACON_ASTMTXK: OSC TCXO 32.768KHZ MEMS SMD; CLASS: DISCRETE; Frequency Stability: 5ppm; Manufacturer: Abracon LLC; Package Size: 0.061" L x 0.033" W (1.54mm x 0.84mm)
Y1 = CRYSTAL: CRYSTAL 16.0000MHZ 18PF SMD; CLASS: DISCRETE; Frequency Stability: 30ppm; Frequency Tolerance: 20ppm; Manufacturer: Abracon LLC; Manufacturer PN: ABM3-16.000MHZ-D2Y-T; PART_NUMBER: ABM3-16.000MHZ-D2Y-T; Package Size: 0.197" L x 0.126" W (5.00mm x 3.20mm)
C?#50 C?#52 C?#57 = CAP: CAP CER 1UF 25V 10% X7R 0603; CLASS: DISCRETE; Dielectric Type: Capacitors; Manufacturer: TDK Corporation; Manufacturer PN: C1608X7R1E105K; PART_NUMBER: C1608X7R1E105K; Package Size: 0603 (1608 Metric); Rated Voltage: 25V; Temperature Coefficient: X7R; Tolerance: ±10%
J5 = HEADER_10: CONN HDR 2MM DUAL W/LATCH 10POS; CLASS: IO; Manufacturer: Harwin Inc
R41 R42 = RES: CLASS: DISCRETE; Manufacturer: Vishay; Manufacturer PN: CRCW06034K70JNEA; PART_NUMBER: CRCW06034K70JNEA; Package Size: 0603; Rated Power: 0.1W; Temperature Coefficient: 200ppm/K; Tolerance: 5%
R?#49 = RES: CLASS: DISCRETE; Manufacturer: Vishay; Manufacturer PN: CRCW060347K0JNEA; PART_NUMBER: CRCW060347K0JNEA; Package Size: 0603; Rated Power: 0.1W; TMP Manufacturer: Vishay; TMP Manufacturer PN: CRCW060347K0JNEA; Temperature Coefficient: 200ppm/K; Tolerance: 5%
R?#54 = RES: CLASS: DISCRETE; Manufacturer: Vishay; Manufacturer PN: CRCW0603825RFKEA; PART_NUMBER: CRCW0603825RFKEA; Package Size: 0603; Rated Power: 0.1W; Temperature Coefficient: 100ppm/K; Tolerance: 1%
R?#58 R?#59 = RES: CLASS: DISCRETE; Manufacturer: Vishay; Manufacturer PN: CRCW060316K2FKEA; PART_NUMBER: CRCW060316K2FKEA; Package Size: 0603; Rated Power: 0.1W; Temperature Coefficient: 100ppm/K; Tolerance: 1%
U19 = FM24CL04B: IC FRAM 4K I2C 1MHZ 8SOIC; CLASS: IC; Manufacturer: Cypress Semiconductor Corp; Package Size: 8-SOIC (0.154", 3.90mm Width); Supply Voltage: 2.7 V ~ 3.6 V
U?#48 = LM60: IC TEMP SENSOR 2.7V SOT23-3; CLASS: IC; Manufacturer: Texas Instruments; Package Size: TO-236-3, SC-59, SOT-23-3; Supply Voltage: 2.7 V ~ 10 V
U?#53 = HIH-503x: HUMIDITY SENSOR SMD 3%; CLASS: IC; Manufacturer: Honeywell Sensing and Control; Supply Voltage: 2.7 V ~ 5.5 V
U?#55 = W25N01GVZEIG
C17 C17#2 C19 C20 = CAP: CLASS: DISCRETE; Dielectric Type: Ceramic; Manufacturer: Kemet; Manufacturer PN: C0603C104K5RAC; PART_NUMBER: C0603C104K5RAC; Package Size: 0603; Rated Voltage: 50V; Temperature Coefficient: X7R; Tolerance: 10%
C18 = CAP: CAP CER 10UF 16V 10% X7R 1206; CLASS: DISCRETE; Dielectric Type: Ceramic; Manufacturer: Kemet; Manufacturer PN: C1206C106K4RACTU; PART_NUMBER: C1206C106K4RAC; Package Size: 1206; Rated Voltage: 16V; Temperature Coefficient: X7R; Tolerance: 10%
Q?#5 = MBT3946DW1T1G: TRANS NPN/PNP 40V 0.2A SC88; CLASS: DISCRETE; Manufacturer: ON Semiconductor; Package Size: 6-TSSOP, SC-88, SOT-363; Polarity: NPN, PNP; Rated Power: 150mW
R17 = RES: RES SMD 10K OHM 1% 1/10W 0603; CLASS: DISCRETE; Manufacturer: Vishay; Manufacturer PN: CRCW060310K0FKEA; PART_NUMBER: CRCW060310K0FKEA; Package Size: 0603; Rated Power: 0.1W; Temperature Coefficient: 100ppm/K; Tolerance: 1%
R27 R28 R?#12 = RES: RES SMD 1M OHM 0.1% 1/8W 0805; CLASS: DISCRETE; Manufacturer: Panasonic Electronic Components; Manufacturer PN: ERA-6AEB105V; PART_NUMBER: ERA-6AEB105V; Package Size: 0805 (2012 Metric); Rated Power: 0.125W, 1/8W; Temperature Coefficient: 25ppm/C; Tolerance: 0.1%
R?#4 R?#7 R?#10 R?#11 = RES: TO BE DETERMINED, HEIGHT 0.022"; CLASS: DISCRETE; PART_NUMBER: TBD_R0603; Package Size: 0603
U6 = ADS1248: IC ADC 24BIT SPI 2KSPS 28TSSOP; CLASS: IC; Manufacturer: Texas Instruments; Package Size: 28-TSSOP (0.173", 4.40mm Width); Supply Voltage: 2.7 V - 5.25 V
C8 C13 C13#2 = CAP: CLASS: DISCRETE; Dielectric Type: Ceramic; Manufacturer: Kemet; Manufacturer PN: C0603C103J3GAC; PART_NUMBER: C0603C103J3GAC; Package Size: 0603; Rated Voltage: 25V; Temperature Coefficient: C0G(NP0); Tolerance: 5%
C4 C14 C14#2 C?#14 = CAP: CLASS: DISCRETE; Dielectric Type: Ceramic; Manufacturer: Kemet; Manufacturer PN: C0603C102J3GAC; PART_NUMBER: C0603C102J3GAC; Package Size: 0603; Rated Voltage: 25V; Temperature Coefficient: C0G(NP0); Tolerance: 5%
C?#6 C?#8 C?#9 = CAP: TO BE DETERMINED, HEIGHT 0.035"; CLASS: DISCRETE; PART_NUMBER: TBD_C0603; Package Size: 0603
J2 = BNC_1C4S: CONN MINI BNC JACK R/A 75OHM PCB; CLASS: IO; Manufacturer: Amphenol RF Division
R15 = RES: CLASS: DISCRETE; Manufacturer: Vishay; Manufacturer PN: CRCW0603499KFKEA; PART_NUMBER: CRCW0603499KFKEA; Package Size: 0603; Rated Power: 0.1W; Temperature Coefficient: 100ppm/K; Tolerance: 1%
U4 = ADG1609B_CP: IC MULTIPLEXER DL 4X1 16LFCSP; CLASS: IC; Manufacturer: Analog Devices Inc.; Package Size: 16-WFQFN Exposed Pad, CSP
J1 = CON12: CONN HDR 2MM R/A W/LATCH 12POS; CLASS: IO; Manufacturer: Harwin Inc
R4 = RES: RES SMD 6.65KOHM 0.1% 1/10W 0603; CLASS: DISCRETE; Manufacturer: Panasonic Electronic Components; Manufacturer PN: ERA-3AEB6651V; PART_NUMBER: ERA-3AEB6651V; Package Size: 0603 (1608 Metric); Rated Power: 0.1W, 1/10W; Temperature Coefficient: 25ppm/C; Tolerance: 0.1%
R5 = RES: CLASS: DISCRETE; Manufacturer: Vishay; Manufacturer PN: CRCW060320K0FKEA; PART_NUMBER: CRCW060320K0FKEA; Package Size: 0603; Rated Power: 0.1W; Temperature Coefficient: 100ppm/K; Tolerance: 1%
R6 = RES: RES SMD 15K OHM 0.1% 1/10W 0603; CLASS: DISCRETE; Manufacturer: Panasonic Electronic Components; Manufacturer PN: ERA-3AEB153V; PART_NUMBER: ERA-3AEB153V; Package Size: 0603 (1608 Metric); Rated Power: 0.1W, 1/10W; Temperature Coefficient: 25ppm/C; Tolerance: 0.1%
R7#2 = RES: RES 100K OHM 1/10W 1% 0603 SMD; CLASS: DISCRETE; Manufacturer: Vishay/Dale; Manufacturer PN: CRCW0603100KFKEA; PART_NUMBER: CRCW0603100KFKEA; Package Size: 0603; Rated Power: 0.1W; Temperature Coefficient: 100ppm/K; Tolerance: 1%
R?#15 R?#18 = RES: CLASS: DISCRETE; Manufacturer: Vishay; Manufacturer PN: CRCW0603133RFKEA; PART_NUMBER: CRCW0603133RFKEA; Package Size: 0603; Rated Power: 0.1W; Temperature Coefficient: 100ppm/K; Tolerance: 1%
U1 U?#13 = LT6656_S6: IC VREF SERIES 1.25V TSOT23-6; CLASS: IC; Manufacturer: Linear Technology; Package Size: SOT-23-6 Thin, TSOT-23-6

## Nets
GND_ISO: BT1.2(-) C1.2 C2.2 C3.2 C4.2 C6.2 C12.2 C13.2 C13#2.2 C14.2 C14#2.2 C15.2 C16.2 C17.2 C17#2.1 C18.1 C19.1 C20.1 C25.2 C25#2.2 C26.2 C27.2 C28.2 C29.2 C30.2 C31.2 C32.2 C32#2.2 C33.2 C33#2.2 C34.2 C?#2.2 C?#3.2 C?#6.2 C?#8.2 C?#9.2 C?#14.2 C?#16.2 C?#17.2 C?#19.1 C?#22.2 C?#23.2 C?#24.2 C?#30.2 C?#31.2 C?#33.2 C?#36.1 C?#43.2 C?#50.2 C?#52.2 C?#57.2 J1.3 J1.4 J1.11 J1.12 J2.2(SHIELD) J2.3(SHIELD2) J2.4(SHIELD3) J2.5(SHIELD4) J3.3 J5.2 J5.3 J5.5 J?#32.3 J?#32.4 Q?#5.1(E2) R4.1 R7.1 R8.1 R10.1 R27.2 R?#49.2 SB2.1 SW1.1 SW1.2 SW2.1 SW2.2 T?#37.2 T?#37.5 T?#37.6 TP2.1(TP) TP?#45.1(TP) U1.1(GND) U1.2(GND) U2.4(V-) U3.4(V-) U4.1(Vss) U4.13(GND) U4.17(PAD) U6.2(DGND2) U6.3(CLK) U6.7(REFP1) U6.8(REFN1) U6.10(VREFCOM) U6.21(AVSS) U7.2(Gnd) U8.1(GND1) U8.4(GND4) U9.2(GND) U19.2(A1) U19.3(A2) U19.4(VSS) U19.7(WP) U?#1.2(GND) U?#13.1(GND) U?#13.2(GND) U?#20.11(GND) U?#20.17(EP) U?#29.4(GND1) U?#29.5(GND2) U?#41.2(GND) U?#47.3(GNDA) U?#47.12(GND1) U?#47.27(GND2) U?#47.35(GNDX) U?#47.39(GND3) U?#47.55(GND4) U?#48.3(GND) U?#53.1(-Ve) U?#55.4(GND)
Vbat: C34.1 R11.1 U?#47.37(VBAT)
VDDC: C25#2.1 C26.1 C27.1 U?#47.25(VDDC1) U?#47.56(VDDC2)
+1P25V: C?#17.1 R7#2.2 R?#12.1 U6.15(AIN6/IEXC//GPIO6) U?#13.6(VOUT)
+2P5V: C1.1 R?#15.2 U1.6(VOUT)
A0: R?#7.2 U6.5(REFP0/GPIO0)
A1: R?#10.2 U6.6(REFN0/GPIO1)
A3P3V: C20.2 C25.1 C?#2.1 R5.1 R?#11.1 U3.8(V+) U6.22(AVDD) U?#1.5(VOUT)
ADC_Reset: U6.4(~{RESET}) U?#47.5(PF4)
Battery: C?#23.1 C?#43.1 J1.2 R6.1 R?#35.1 R?#46.1 T?#37.3 TP1.1(TP) U4.10(S2B) U?#41.5(VIN)
Bias+: C2.1 C3.1 C4.1 C6.1 C?#14.1 C?#16.1 J3.2 Q?#5.4(E1) U1.4(VIN) U2.8(V+) U4.12(Vdd) U?#13.4(VIN)
C3P3V: C12.1 C13.1 C14.1 C15.1 C16.1 C17.1 C28.1 C29.1 C30.1 C31.1 C33.1 C?#30.1 R41.1 R42.1 R?#4.1 SB1.2 SB5.1 U7.5(Vdd) U9.5(VOUT) U19.8(VDD) U?#29.8(Vdd2) U?#47.2(VDDA) U?#47.11(VDD1) U?#47.26(VDD2) U?#47.42(VDD3) U?#47.54(VDD4) U?#55.3(~{WP}) U?#55.8(VCC)
Counter B: C8.1 R6.2 U2.7(OUT) U4.3(S2A)
drain: J1.9 R4.2 U2.5(IN+)
DRDY: U6.25(~{DRDY}) U?#47.53(PD6)
EnvEnable: R?#54.1 U?#47.57(PB5)
FLASH_CLK: U?#47.19(PA2) U?#55.6(CLK)
FLASH_CS: U?#47.20(PA3) U?#55.1(~{CS})
FLASH_HOLD: U?#47.24(PA7) U?#55.7(~{HOLD})
FLASH_MISO: U?#47.21(PA4) U?#55.2(DO)
FLASH_MOSI: U?#47.22(PA5) U?#55.5(DI)
Green_LED: D4.A U?#47.14(PC6)
HIB: U?#47.33(~{HIB})
Humidity: C?#57.1 R?#59.2 TP?#51.1(TP) U?#47.7(PE2)
I3P5V: C?#22.1 C?#31.1 D?#34.C R?#40.2 U?#20.9(FORCEON) U?#20.12(VCC) U?#20.13(~{FORCEOFF}) U?#29.1(Vdd1)
MISO: U6.26(DOUT/~{DRDY}) U?#47.63(PD2)
MOSI: U6.27(DIN) U?#47.64(PD3)
NVRAM_SCL: R41.2 U19.6(SCL) U?#47.47(PB2)
NVRAM_SDA: R42.2 U19.5(SDA) U?#47.48(PB3)
OSC0: C32#2.1 U?#47.40(OSC0) Y1.1
OSC1: C33#2.1 U?#47.41(OSC1) Y1.2
PA0_Console_RX: U?#29.6(Vob) U?#47.17(PA0)
PA1_Console_TX: U?#29.7(Via) U?#47.18(PA1)
PC0_TCK: J5.7 U?#47.52(PC0)
PC1_TMS: J5.6 U?#47.51(PC1)
PC2_TDI: J5.9 U?#47.50(PC2)
PC3_TDO: J5.8 U?#47.49(PC3)
ph+: U4.6(DA) U6.14(AIN5/IEXC/GPIO5)
ph-: U3.6(IN-) U3.7(OUT) U6.12(AIN1/IEXC)
R3P5V: C32.1 C?#3.1 C?#19.2 C?#36.2 C?#38.2 D?#27.C TP?#26.1(TP) U9.1(VIN) U9.3(EN) U?#1.1(VIN) U?#1.3(EN)
Red_LED: D3.A U?#47.13(PC7)
ReferenceE: C13#2.1 J2.1(CENTER) R9.2 R15.1
ReferenceI: J1.6
RESET: J5.10 U7.4(\\~{RESE}T) U?#47.38(~{RST})
rko-b: J1.7
SCLK: U6.28(SCLK) U?#47.61(PD0)
Source: J1.1 R?#18.1 U4.2(S1A) U4.4(S3A)
SS: U6.24(~{CS}) U?#47.62(PD1)
Start: U6.23(START) U?#47.1(PB6)
Substrate: J1.8 R?#12.2 U4.9(S3B)
T3: J1.5 R17.1
Temperature: C?#50.1 R?#58.2 TP?#56.1(TP) U?#47.8(PE1)
Wake: R10.2 R12.1 SW2.3 SW2.4 U?#47.32(~{WAKE})
XOSC0: U8.2(CLK) U?#47.34(XOSC0)
N3536495: R9.1 SW1.3 SW1.4 U7.3(\\~{M}R)
N3539619: SB1.1 SB2.2 U7.1(CT)
N3632478: BT1.1(+) R11.2 R12.2 U8.3(VDD)
N3682711: D4.C R8.2
N3682795: D3.C R7.2
N3710447: C17#2.2 R?#4.2 U6.1(DVDD)
N3710661: C18.2 U6.9(VREFOUT)
N3725523: C19.2 R17.2 U6.11(AIN0/IEXC)
N3746895: C8.2 R7#2.1 U2.6(IN-)
N3747143: J1.10 R5.2
N3750476: C14#2.1 R15.2 U2.3(IN+)
N3750849: U2.1(OUT) U2.2(IN-) U4.11(S1B)
N3752723: U3.5(IN+) U4.7(DB)
N3754157: C?#6.1 R?#7.1 U4.15(A0)
N3754164: C?#8.1 R?#10.1 U4.14(A1)
N3775591: J5.1 SB5.2
N3866027: R24.2 U6.18(AIN3/IEXC/GPIO3)
N3866043: R27.1 R28.2 U6.16(AIN7/IEXC/GPIO7)
N3956660: C?#39.1 R?#35.2
N3956664: C?#39.2 R?#25.1 T?#37.4 U?#41.4(SW)
N3956748: R?#46.2 U?#41.1(EN)
N3956790: D?#27.A R?#21.1 T?#37.7 T?#37.8
N3956924: R?#25.2 U?#41.3(RFB)
N3956930: C?#38.1 R?#21.2
N3957299: C?#42.1 D?#34.A T?#37.1
N3957473: C?#42.2 R?#40.1
N3960086: C?#52.1 R?#54.2 U?#48.1(Vs+) U?#53.3(+Ve)
N3960190: R?#58.1 U?#48.2(Vo)
N3960350: R?#49.1 R?#59.1 U?#53.2(OUT)
N3965186: U?#20.8(T1IN) U?#29.2(Voa)
N3965196: U?#20.6(R1OUT) U?#29.3(Vib)
N3965303: J?#32.2 U?#20.10(T1OUT)
N3965313: J?#32.1 U?#20.5(R1IN)
N3974606: R?#15.1 R?#18.2
N3975191: C?#9.1 R?#11.2 U4.16(EN)
N3984624: C?#44.1 U?#20.16(C1+)
N3984631: C?#44.2 U?#20.1(C1-)
N3984641: C?#28.1 U?#20.2(C2+)
N3984649: C?#33.1 U?#20.4(V-)
N3984661: C?#24.1 U?#20.15(V+)
N3984842: C?#28.2 U?#20.3(C2-)
N3989093: Q?#5.5(B1) Q?#5.6(C2)
N3989219: Q?#5.2(B2) R24.1
N3989273: Q?#5.3(C1) R28.1

Not connected (* = marked no-connect by the designer): J3 1 4; J5 4*; U4 5(S4A) 8(S4B); U6 13(AIN4/IEXC/GPIO4) 17(AIN2/IEXC/GPIO2) 19(IEXC2) 20(IEXC1); U9 4(NC); U19 1(NC); U?#1 4(NC); U?#20 7(~{INVALID}) 14(READY); U?#47 4(PB7) 6(PE3) 9(PE0) 10(PD7) 15(PC5) 16(PC4) 23(PA6) 28(PF0) 29(PF1) 30(PF2) 31(PF3) 36(XOSC1) 43(PD4) 44(PD5) 45(PB0) 46(PB1) 58(PB4) 59(PE4) 60(PE5)

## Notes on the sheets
sheet 1
- Controller and digital power
- DuraFET isolated Bias power
- Analog and ADC power
sheet 2
- GPIO1 GPIO0   Switch          AIN5         AIN1
    0     0        1         pH offset     Ext Ref
    0     1        2         Counter B     Counter A
    1     0        3         Source        Substrate
    1     1        4         pH offset     Int Ref
- GPIO3 -> Bias meas. Enable
- ISFET Temperature -> AIN0
  GND -> AIN6
  BIAS Battery -> AIN7
  Bias Battery Select -> GPIO3
                      -> float = Off
                      -> 0 = off (mphox Bias-)
                      -> 1 = Bias+
- Bias Battery Measurement
sheet 3
- A1    A0   Switch          SxA           SxB
  0     0        1           Source        Ext Ref
  0     1        2           Counter B     Counter A
  1     0        3           Source        Substrate
  1     1        4           NC            NC
sheet 4
- Change to 2.5V
- Change to 1.25
- 2.5V
- 188uA
- 50mV
- 266
- External electrode Reference potential
  FET Source terminal
  2.45V
- 1.25V
- 2.5-0.05-1.25 = 1.2V
- Substrate
- Virtual 1.25V
- 6.65k
- J1      Name                 Color
  1      Source              Orange
  2      Counter A           White/Black
  3      rko-a               Green
  4      T1                  Red/Black
  5      T3                  Orange/Black
  6      Reference           Black
  7      rko-b               Green/Black
  8      Substrate           Red
  9      Drain               Brown
  10     T2                  White
sheet 5
- A possible alternative is a Wurth 750311559
- DE9-S
  3
  2
  5
- Console Rx
  Console Tx
  Console Gnd
sheet 6
- debug
- FRAM
sheet 7
- Place close to VDD and GND pins
- Place in general area TM4C
- Place close to Pins 2 and 3
  VDDA and GNDA
- Place close to VDDC pins 25 and 56
- 200mS
- ~25nA
- 10mS
- Reset
- Place Y and C's close to TM4C
- CR1632 with keystone 504TR holder
- Wake
sheet 8
- 10Hz
- Iq=0.1mA
- VOut= (+6.25 mV/°C × T °C) + 424 mV
- 10Hz
- Iq=0.5mA
- VOUT=(VSUPPLY)(0.00636(sensor RH) + 0.1515), typical at 25C
- SPI Flash
- Debugger
- Non-Volatile Memory
- PB2
- PB3
- Bigger FRAM
- https://www.digikey.com/product-detail/en/fujitsu-electronics-america-inc/MB85RC1MTPNF-G-JNERE1/865-1268-1-ND/5456442
